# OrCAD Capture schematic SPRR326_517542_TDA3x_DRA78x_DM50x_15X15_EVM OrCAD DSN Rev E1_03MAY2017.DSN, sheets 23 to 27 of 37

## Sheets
23 SH31 - VIN HDMI IN-1: size C; rev: C1
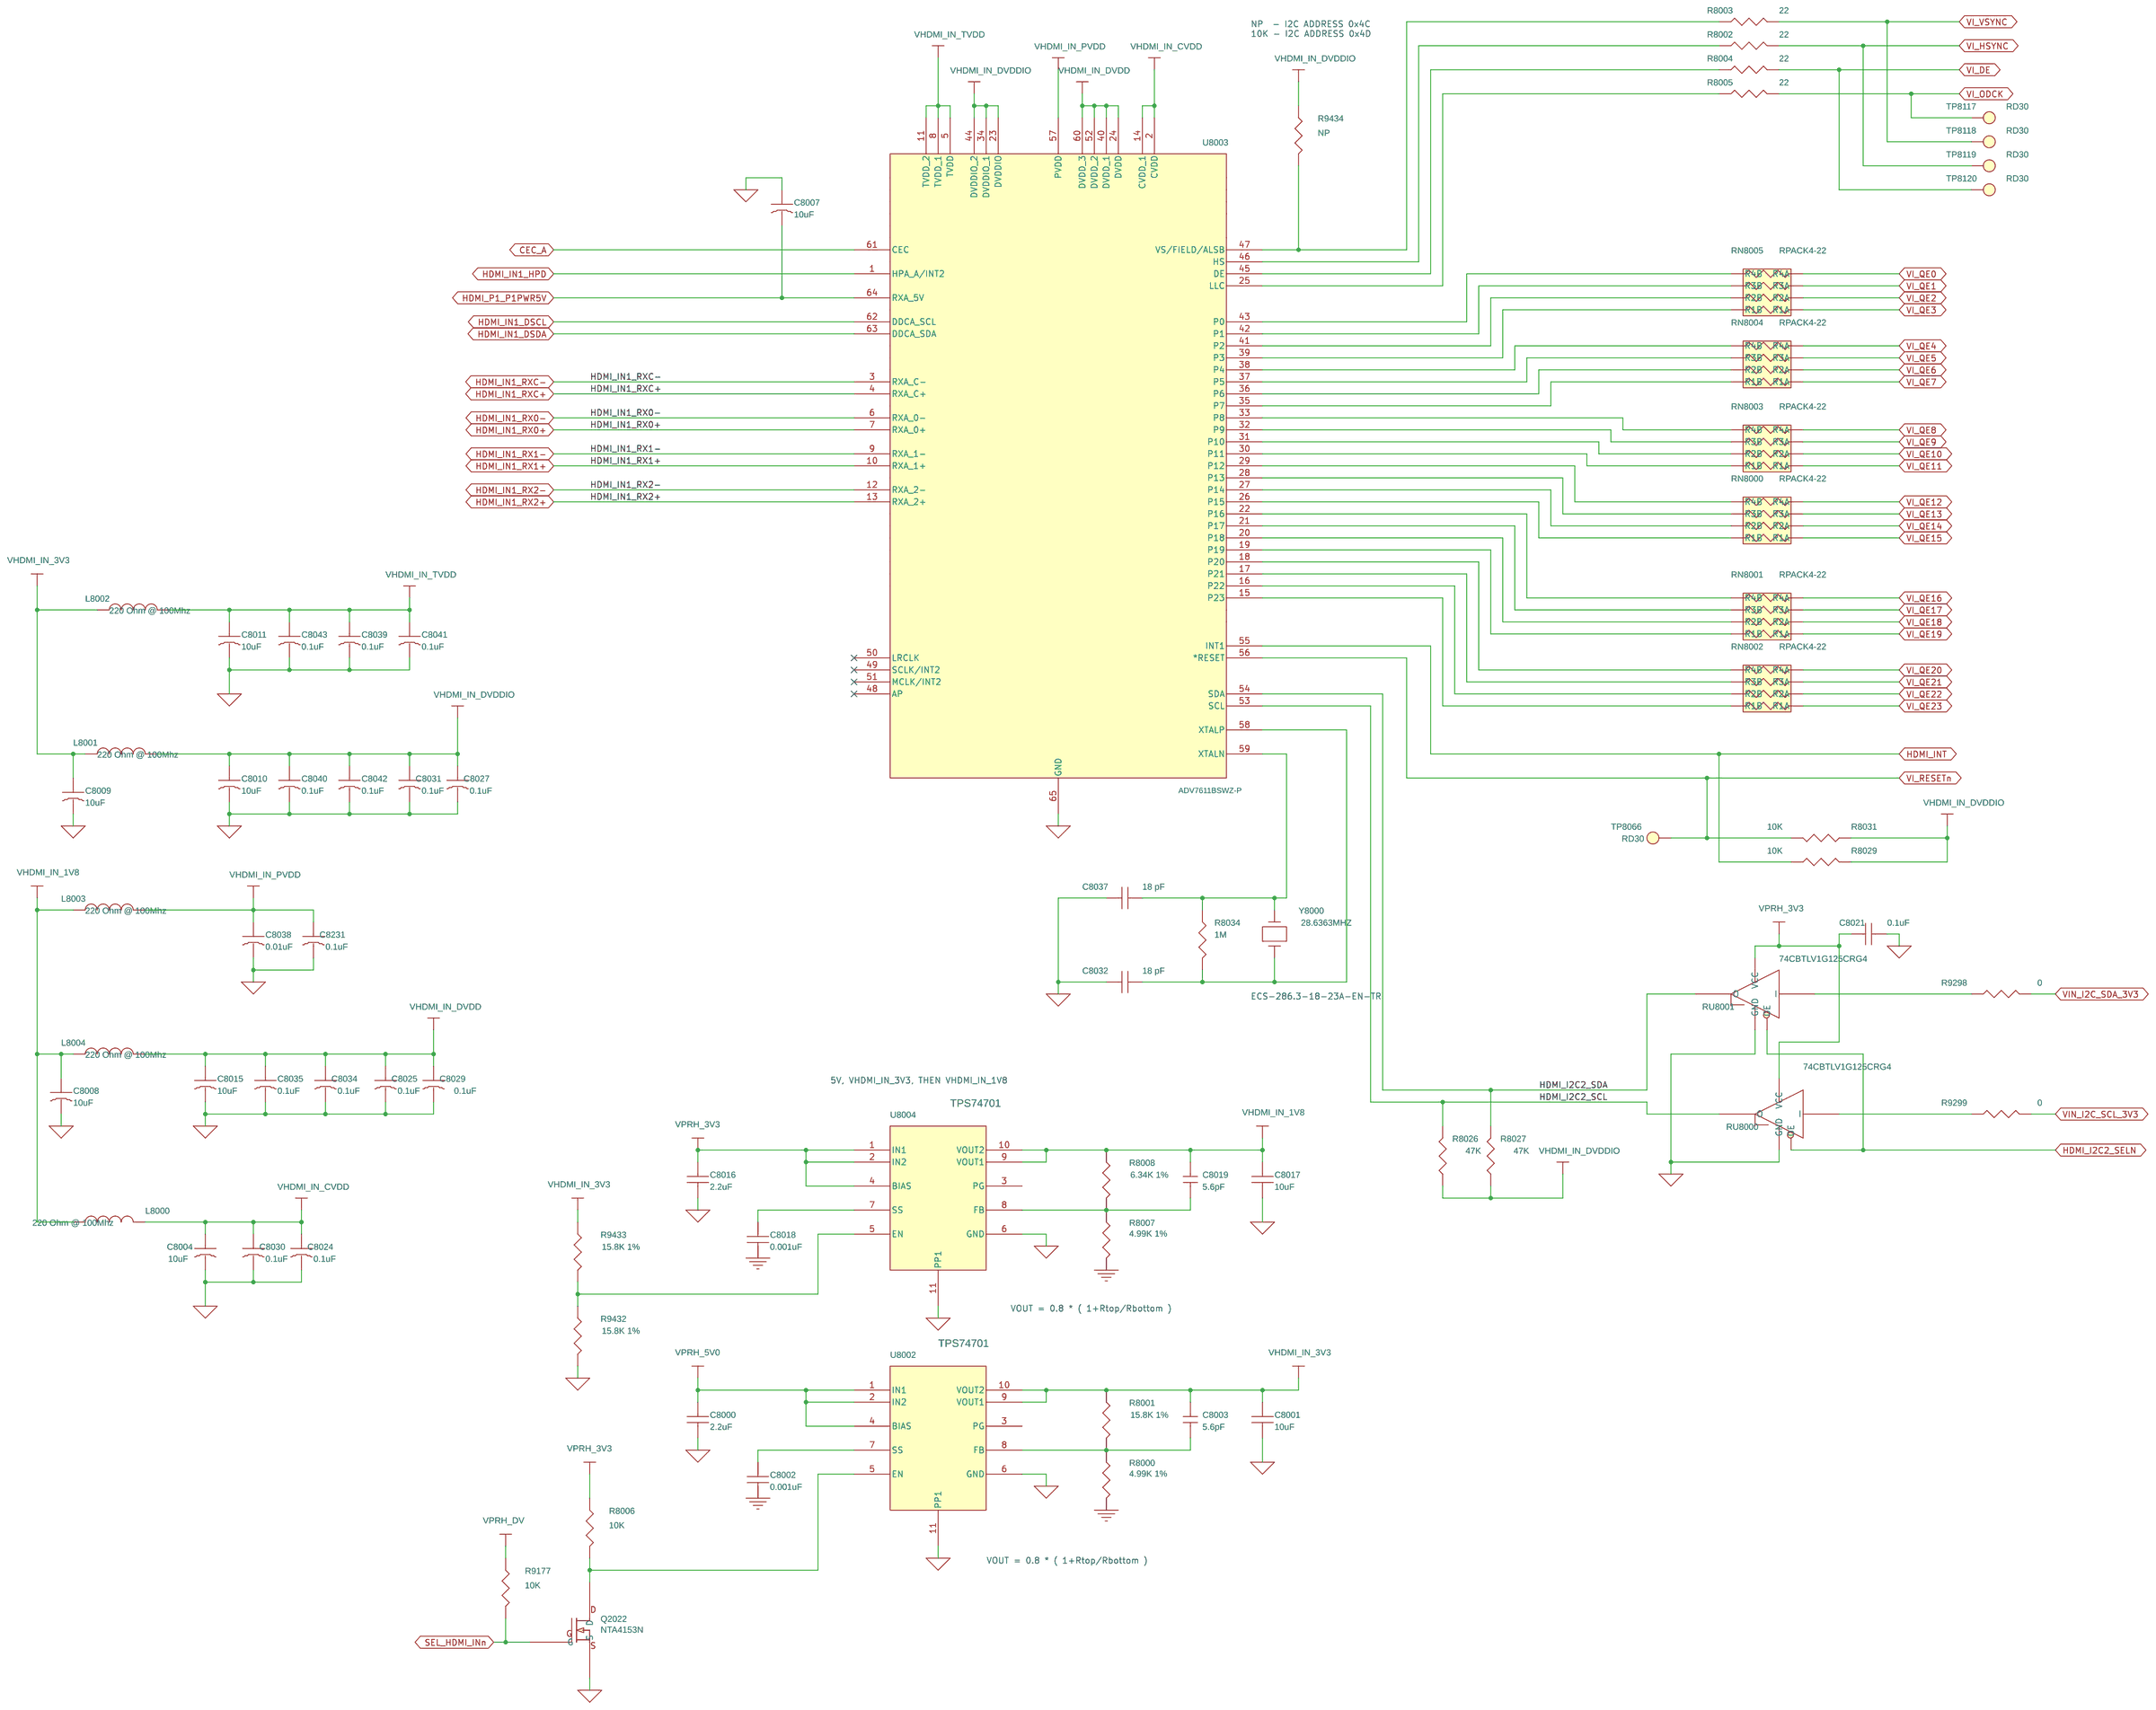
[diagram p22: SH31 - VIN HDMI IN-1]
24 SH32 - VIN HDMI IN-2: rev: B
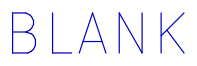
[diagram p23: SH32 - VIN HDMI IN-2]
25 SH33 - VIN HDMI IN-3: size C; rev: C1
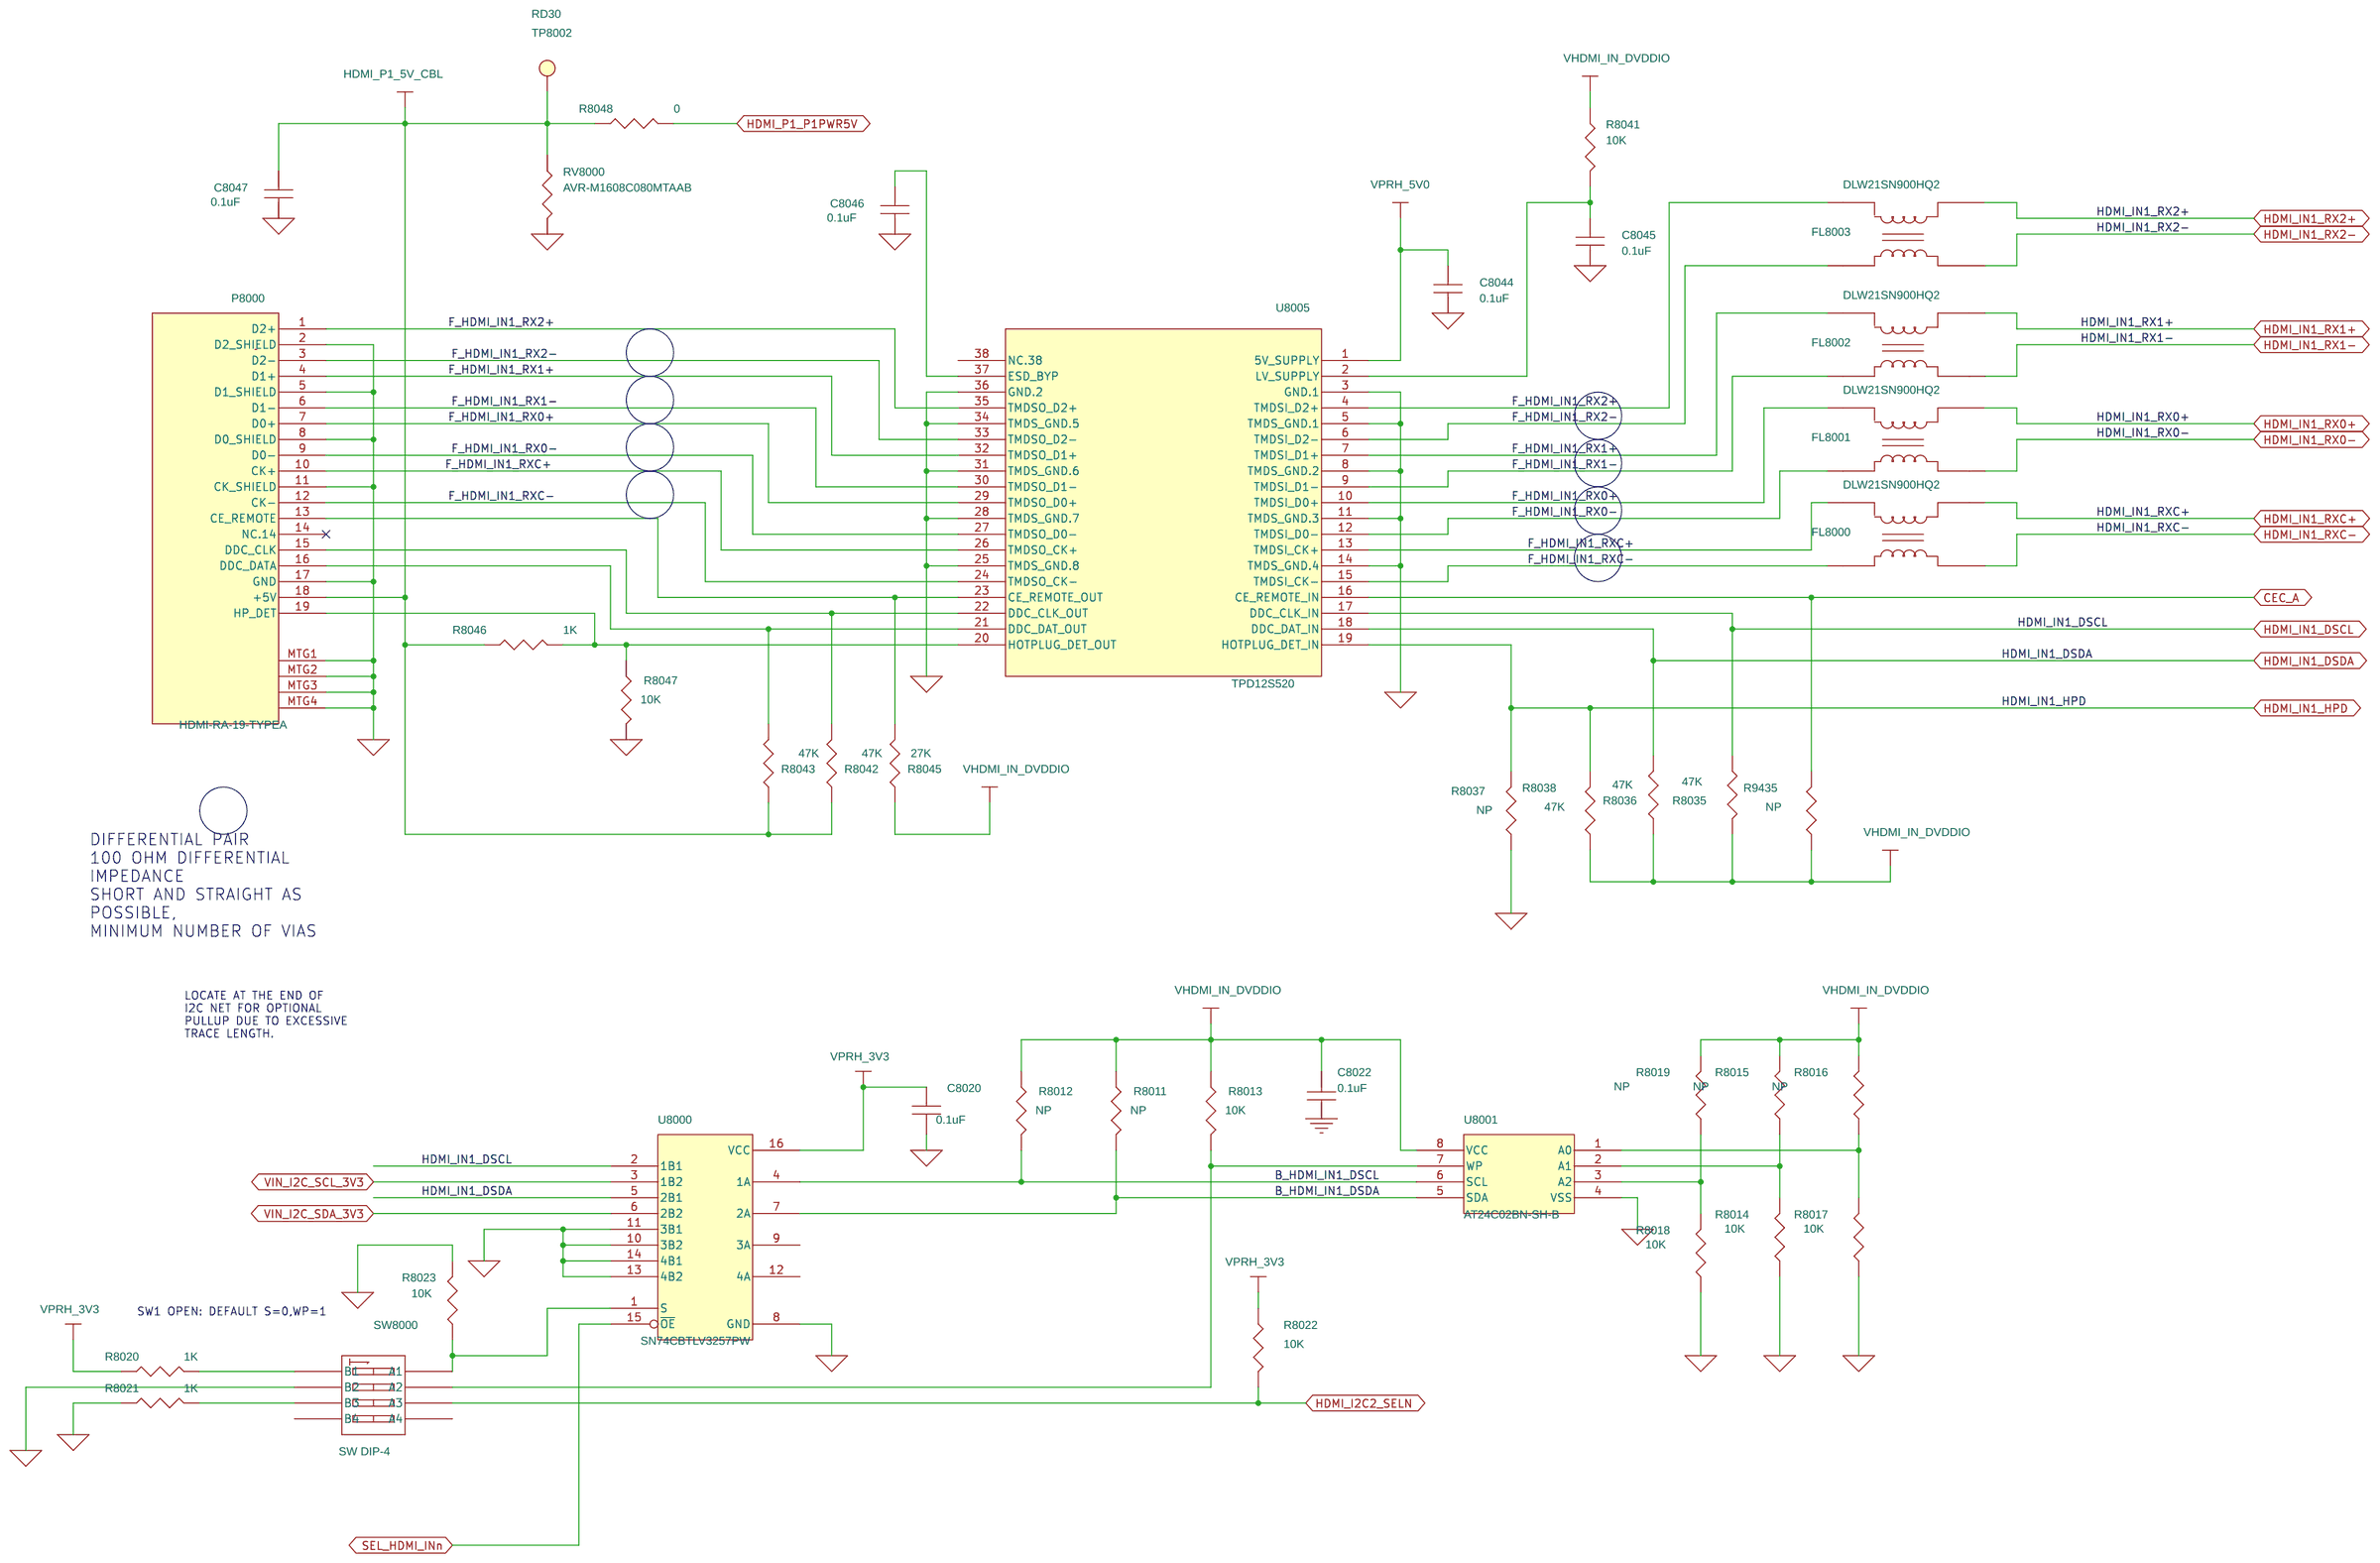
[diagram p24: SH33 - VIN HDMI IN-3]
26 SH34 - CPLD VOUT-1: size C; rev: B
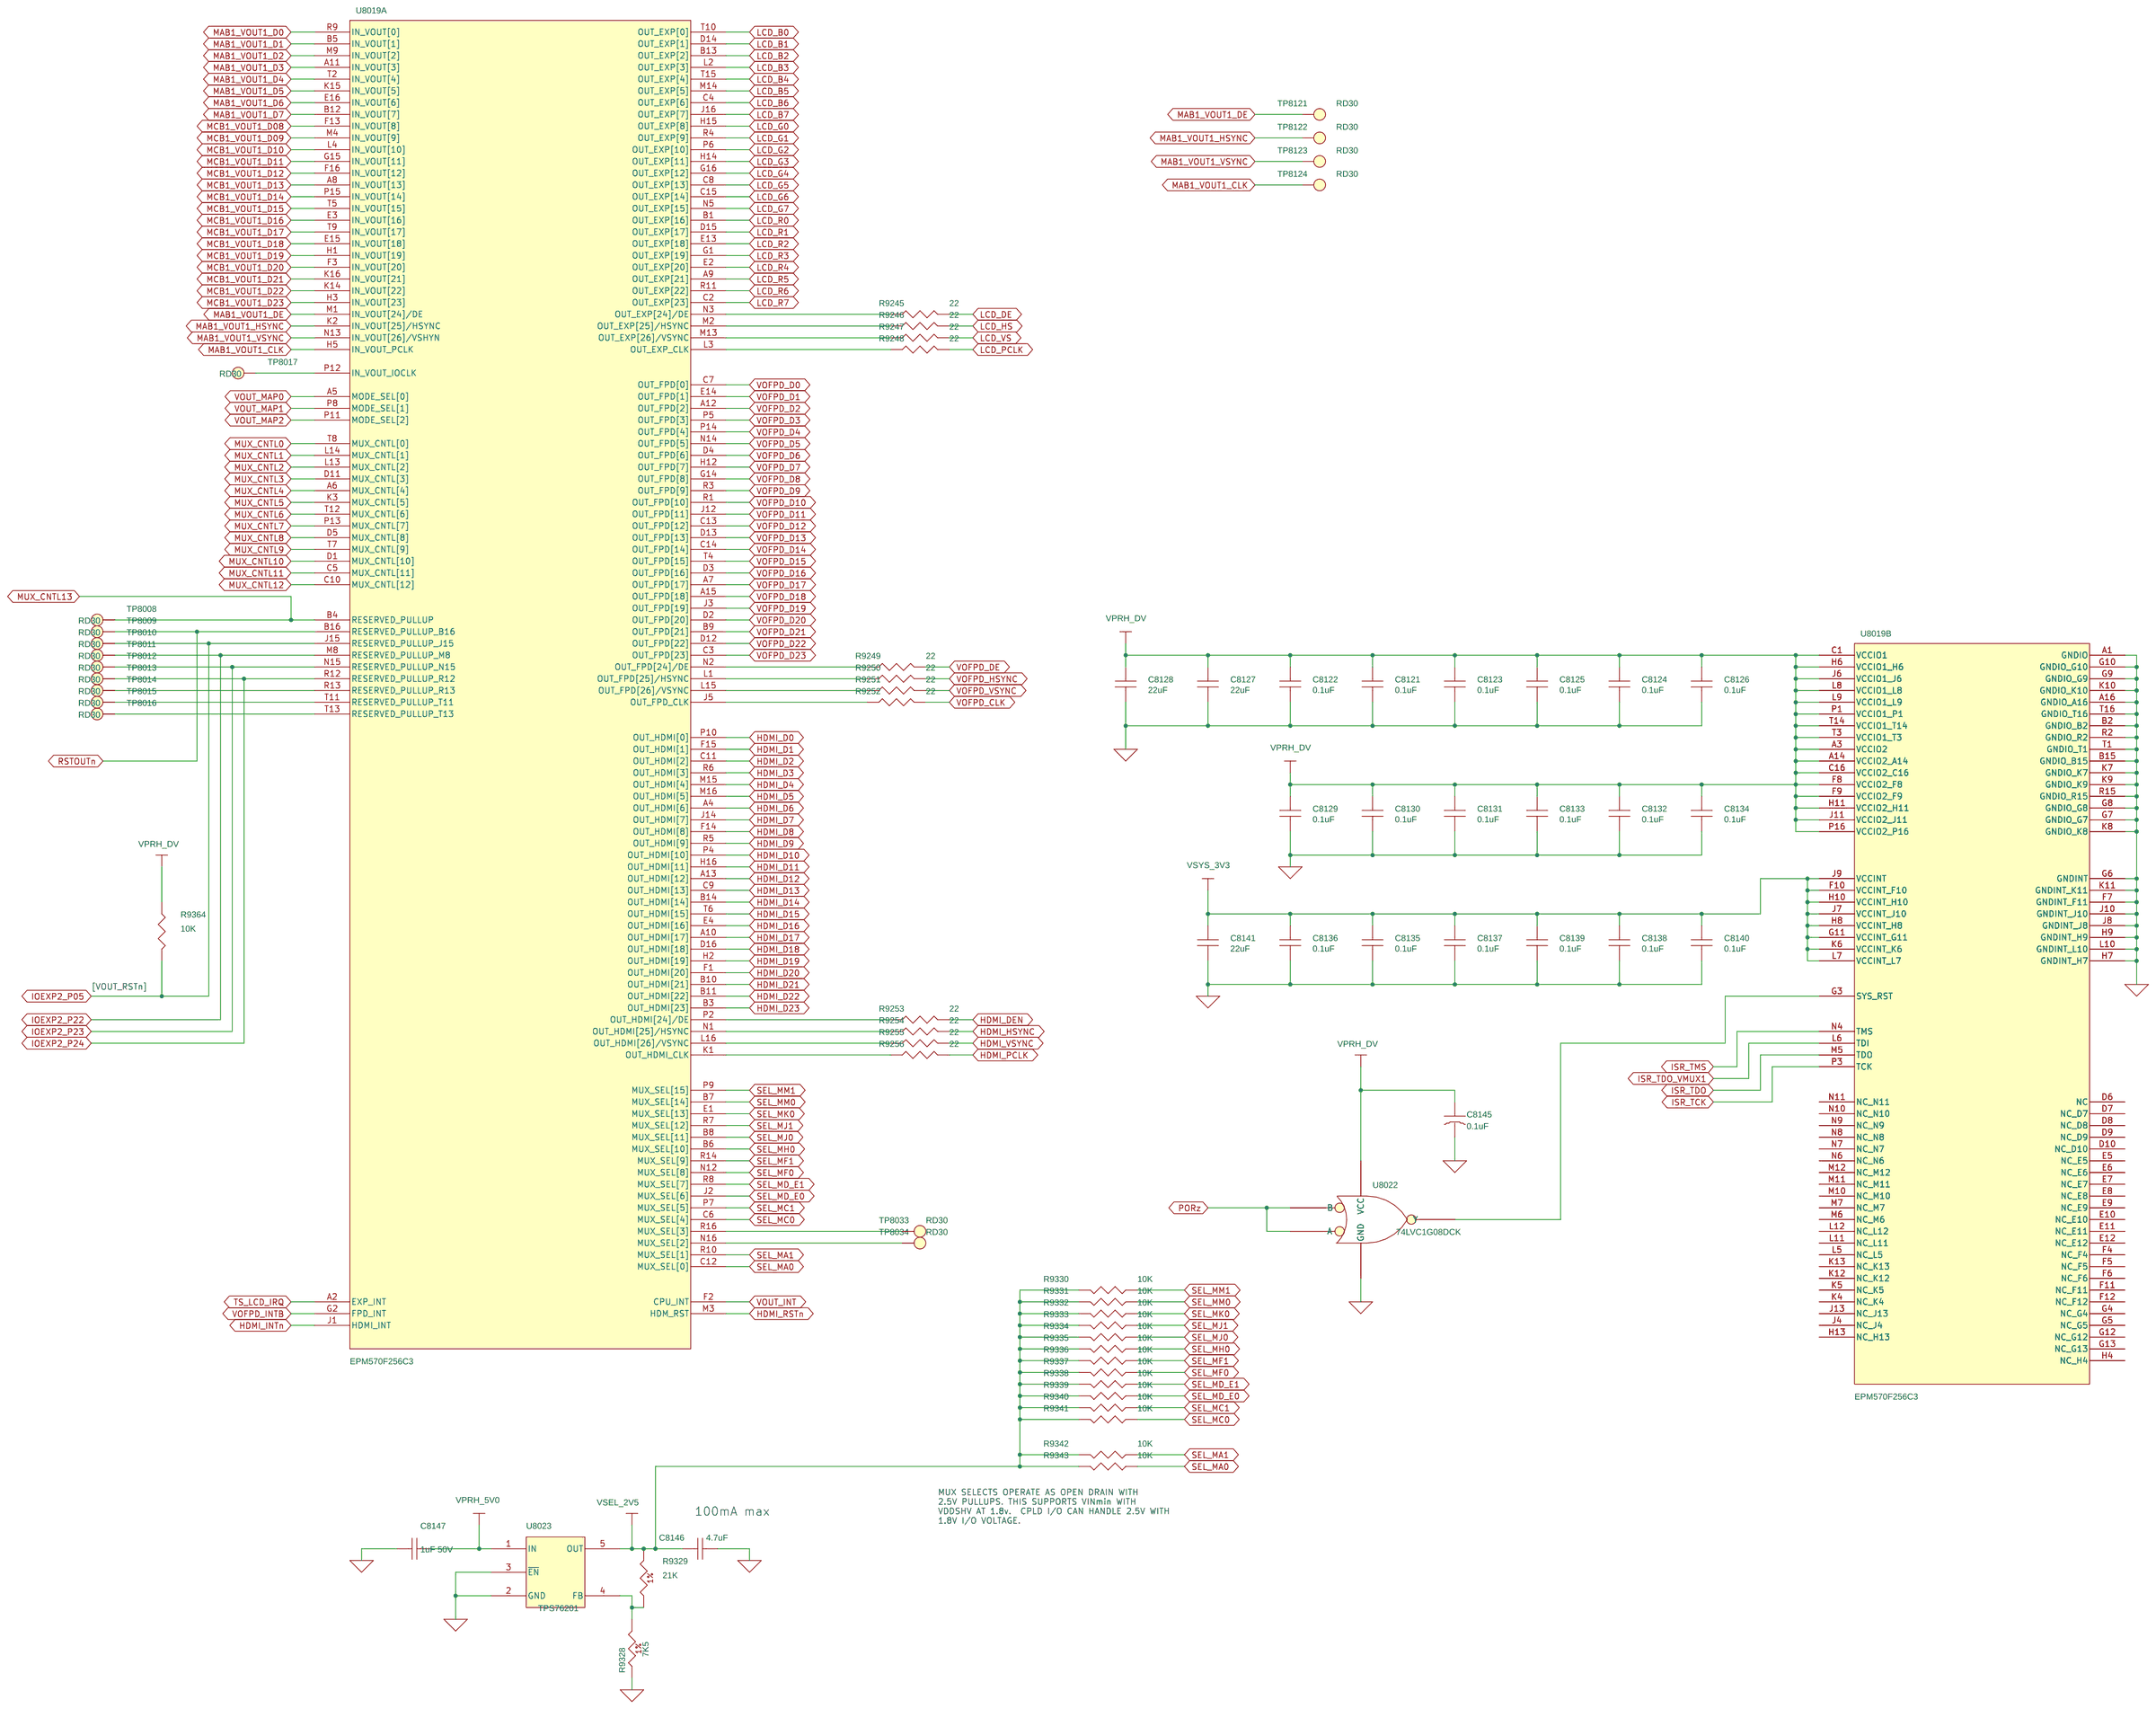
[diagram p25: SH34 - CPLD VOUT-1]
27 SH35 - CPLD VIN-1: size C; rev: B
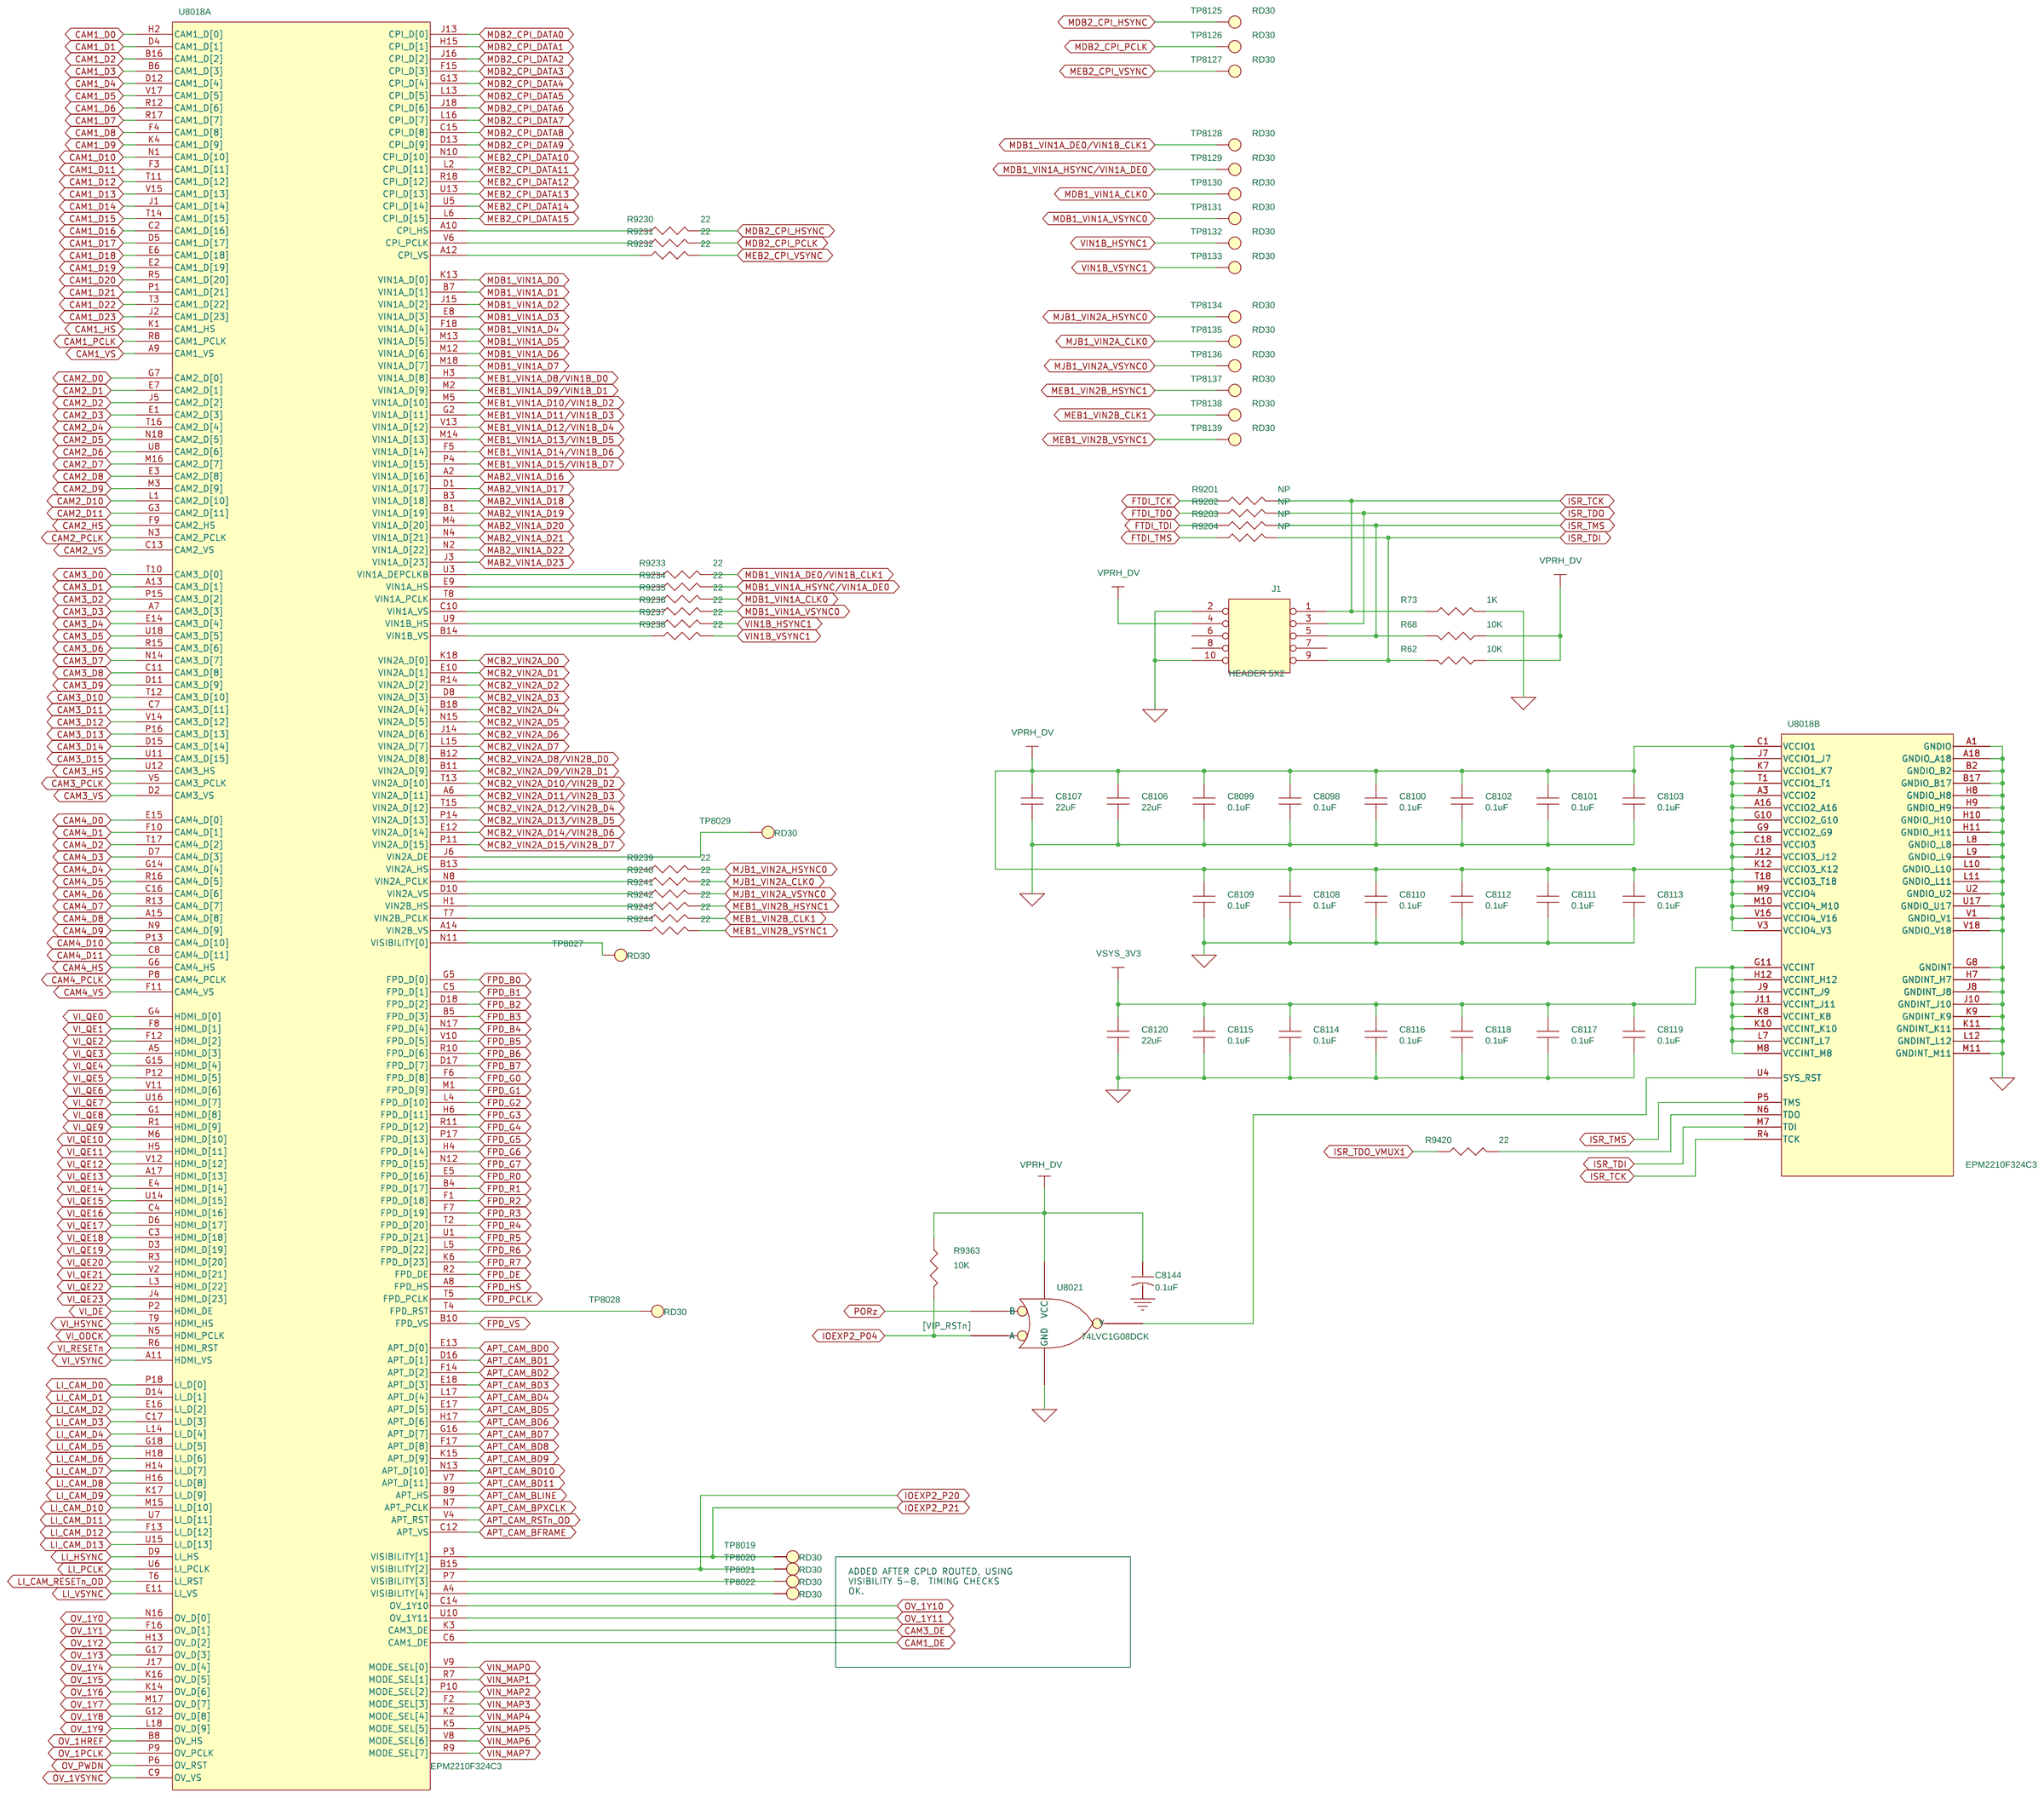
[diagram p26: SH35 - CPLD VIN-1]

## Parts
sheet SH31 - VIN HDMI IN-1
C8000  2.2uF  [c603-35x45]
C8001  10uF  [c603-35x45]
C8002  0.001uF  [c402-25]
C8003  5.6pF  [c402-25]
C8004  10uF  [c603-35x45]
C8007  10uF  [c603-35x45]
C8008  10uF  [c603-35x45]
C8009  10uF  [c603-35x45]
C8010  10uF  [c603-35x45]
C8011  10uF  [c603-35x45]
C8015  10uF  [c603-35x45]
C8016  2.2uF  [c603-35x45]
C8017  10uF  [c603-35x45]
C8018  0.001uF  [c402-25]
C8019  5.6pF  [c402-25]
C8021  0.1uF  [c402-25]
C8024  0.1uF  [c402-25]
C8025  0.1uF  [c402-25]
C8027  0.1uF  [c402-25]
C8029  0.1uF  [c402-25]
C8030  0.1uF  [c402-25]
C8031  0.1uF  [c402-25]
C8032  18 pF  [c402-25]
C8034  0.1uF  [c402-25]
C8035  0.1uF  [c402-25]
C8037  18 pF  [c402-25]
C8038  0.01uF  [c402-25]
C8039  0.1uF  [c402-25]
C8040  0.1uF  [c402-25]
C8041  0.1uF  [c402-25]
C8042  0.1uF  [c402-25]
C8043  0.1uF  [c402-25]
C8231  0.1uF  [c402-25]
L8000  220 Ohm @ 100Mhz  [l805-35x60]
L8001  220 Ohm @ 100Mhz  [l805-35x60]
L8002  220 Ohm @ 100Mhz  [l805-35x60]
L8003  220 Ohm @ 100Mhz  [l805-35x60]
L8004  220 Ohm @ 100Mhz  [l805-35x60]
Q2022  NTA4153N  [SC-75]
R8000  4.99K 1%  [r603-35x45]
R8001  15.8K 1%  [r603-35x45]
R8002  22  [r402-25]
R8003  22  [r402-25]
R8004  22  [r402-25]
R8005  22  [r402-25]
R8006  10K  [r402-25]
R8007  4.99K 1%  [r603-35x45]
R8008  6.34K 1%  [r603-35x45]
R8026  47K  [r402-25]
R8027  47K  [r402-25]
R8029  10K  [r402-25]
R8031  10K  [r402-25]
R8034  1M  [r402-25]
R9177  10K  [r402-25]
R9298  0  [r201-6p6spc]
R9299  0  [r201-6p6spc]
R9432  15.8K 1%  [r603-35x45]
R9433  15.8K 1%  [r603-35x45]
R9434  NP  [r402-25]
RN8000  RPACK4-22  [rpak8-10x25-28v]
RN8001  RPACK4-22  [rpak8-10x25-28v]
RN8002  RPACK4-22  [rpak8-10x25-28v]
RN8003  RPACK4-22  [rpak8-10x25-28v]
RN8004  RPACK4-22  [rpak8-10x25-28v]
RN8005  RPACK4-22  [rpak8-10x25-28v]
RU8000  74CBTLV1G125CRG4  [dck-5]
RU8001  74CBTLV1G125CRG4  [dck-5]
TP8066  RD30  [tp-30RD13]
TP8117  RD30  [tp-30RD13]
TP8118  RD30  [tp-30RD13]
TP8119  RD30  [tp-30RD13]
TP8120  RD30  [tp-30RD13]
U8002  TPS74701  [drc10-11x33]
U8003  ADV7611BSWZ-P  [lqfp64-10mm-sq-slug]
U8004  TPS74701  [drc10-11x33]
Y8000  28.6363MHZ  [xtal2-75x94]
sheet SH33 - VIN HDMI IN-3
C8020  0.1uF  [c402-25]
C8022  0.1uF  [c402-25]
C8044  0.1uF  [c402-25]
C8045  0.1uF  [c402-25]
C8046  0.1uF  [c402-25]
C8047  0.1uF  [c402-25]
FL8000  DLW21SN900HQ2  [EMI-36X15-DLW21]
FL8001  DLW21SN900HQ2  [EMI-36X15-DLW21]
FL8002  DLW21SN900HQ2  [EMI-36X15-DLW21]
FL8003  DLW21SN900HQ2  [EMI-36X15-DLW21]
P8000  HDMI-RA-19-TYPEA  [hdmi-smt-w-flange-rdpads]
R8011  NP  [r402-25]
R8012  NP  [r402-25]
R8013  10K  [r402-25]
R8014  10K  [r402-25]
R8015  NP  [r402-25]
R8016  NP  [r402-25]
R8017  10K  [r402-25]
R8018  10K  [r402-25]
R8019  NP  [r402-25]
R8020  1K  [r402-25]
R8021  1K  [r402-25]
R8022  10K  [r402-25]
R8023  10K  [r402-25]
R8035  47K  [r402-25]
R8036  47K  [r402-25]
R8037  NP  [r402-25]
R8038  47K  [r402-25]
R8041  10K  [r402-25]
R8042  47K  [r402-25]
R8043  47K  [r402-25]
R8045  27K  [r402-25]
R8046  1K  [r402-25]
R8047  10K  [r402-25]
R8048  0  [r402-25]
R9435  NP  [r402-25]
RV8000  AVR-M1608C080MTAAB  [r603-35x45]
SW8000  SW DIP-4  [sw4-30x50-tda]
TP8002  RD30  [tp-30RD13]
U8000  SN74CBTLV3257PW  [tssop16-14x70]
U8001  AT24C02BN-SH-B  [so8-25x75]
U8005  TPD12S520  [dbt38-12x70]
sheet SH34 - CPLD VOUT-1
C8121  0.1uF  [c402-25rd]
C8122  0.1uF  [c402-25rd]
C8123  0.1uF  [c402-25rd]
C8124  0.1uF  [c402-25rd]
C8125  0.1uF  [c402-25rd]
C8126  0.1uF  [c402-25rd]
C8127  22uF  [c1206-40x70]
C8128  22uF  [c1206-40x70]
C8129  0.1uF  [c402-25rd]
C8130  0.1uF  [c402-25rd]
C8131  0.1uF  [c402-25rd]
C8132  0.1uF  [c402-25rd]
C8133  0.1uF  [c402-25rd]
C8134  0.1uF  [c402-25rd]
C8135  0.1uF  [c402-25rd]
C8136  0.1uF  [c402-25rd]
C8137  0.1uF  [c402-25rd]
C8138  0.1uF  [c402-25rd]
C8139  0.1uF  [c402-25rd]
C8140  0.1uF  [c402-25rd]
C8141  22uF  [c1206-40x70]
C8145  0.1uF  [c402-25]
C8146  4.7uF  [C805-35X60]
C8147  1uF 50V  [c805-35x60]
R9245  22  [r402-25]
R9246  22  [r402-25]
R9247  22  [r402-25]
R9248  22  [r402-25]
R9249  22  [r402-25]
R9250  22  [r402-25]
R9251  22  [r402-25]
R9252  22  [r402-25]
R9253  22  [r402-25]
R9254  22  [r402-25]
R9255  22  [r402-25]
R9256  22  [r402-25]
R9328  7K5  [r603-35X45]
R9329  21K  [r603-35X45]
R9330  10K  [r402-25]
R9331  10K  [r402-25]
R9332  10K  [r402-25]
R9333  10K  [r402-25]
R9334  10K  [r402-25]
R9335  10K  [r402-25]
R9336  10K  [r402-25]
R9337  10K  [r402-25]
R9338  10K  [r402-25]
R9339  10K  [r402-25]
R9340  10K  [r402-25]
R9341  10K  [r402-25]
R9342  10K  [r402-25]
R9343  10K  [r402-25]
R9364  10K  [r402-25]
TP8008  RD30  [tp-30RD13]
TP8009  RD30  [tp-30RD13]
TP8010  RD30  [tp-30RD13]
TP8011  RD30  [tp-30RD13]
TP8012  RD30  [tp-30RD13]
TP8013  RD30  [tp-30RD13]
TP8014  RD30  [tp-30RD13]
TP8015  RD30  [tp-30RD13]
TP8016  RD30  [tp-30RD13]
TP8017  RD30  [tp-30RD13]
TP8033  RD30  [tp-30RD13]
TP8034  RD30  [tp-30RD13]
TP8121  RD30  [tp-30RD13]
TP8122  RD30  [tp-30RD13]
TP8123  RD30  [tp-30RD13]
TP8124  RD30  [tp-30RD13]
U8019  EPM570F256C3  [bga256-18rd]  (sections A,B)
U8022  74LVC1G08DCK  [dck-5]
U8023  TPS76201  [dbv-20x60-5]
sheet SH35 - CPLD VIN-1
C8098  0.1uF  [c402-25rd]
C8099  0.1uF  [c402-25rd]
C8100  0.1uF  [c402-25rd]
C8101  0.1uF  [c402-25rd]
C8102  0.1uF  [c402-25rd]
C8103  0.1uF  [c402-25rd]
C8106  22uF  [c1206-40x70]
C8107  22uF  [c1206-40x70]
C8108  0.1uF  [c402-25rd]
C8109  0.1uF  [c402-25rd]
C8110  0.1uF  [c402-25rd]
C8111  0.1uF  [c402-25rd]
C8112  0.1uF  [c402-25rd]
C8113  0.1uF  [c402-25rd]
C8114  0.1uF  [c402-25rd]
C8115  0.1uF  [c402-25rd]
C8116  0.1uF  [c402-25rd]
C8117  0.1uF  [c402-25rd]
C8118  0.1uF  [c402-25rd]
C8119  0.1uF  [c402-25rd]
C8120  22uF  [c1206-40x70]
C8144  0.1uF  [c402-25]
J1  HEADER 5X2  [JUMP2X5-6040]
R62  10K  [r402-25]
R68  10K  [r402-25]
R73  1K  [r402-25]
R9201  NP  [r402-25]
R9202  NP  [r402-25]
R9203  NP  [r402-25]
R9204  NP  [r402-25]
R9230  22  [r402-25]
R9231  22  [r402-25]
R9232  22  [r402-25]
R9233  22  [r402-25]
R9234  22  [r402-25]
R9235  22  [r402-25]
R9236  22  [r402-25]
R9237  22  [r402-25]
R9238  22  [r402-25]
R9239  22  [r402-25]
R9240  22  [r402-25]
R9241  22  [r402-25]
R9242  22  [r402-25]
R9243  22  [r402-25]
R9244  22  [r402-25]
R9363  10K  [r402-25]
R9420  22  [r402-25]
TP8019  RD30  [tp-30RD13]
TP8020  RD30  [tp-30RD13]
TP8021  RD30  [tp-30RD13]
TP8022  RD30  [tp-30RD13]
TP8027  RD30  [tp-30RD13]
TP8028  RD30  [tp-30RD13]
TP8029  RD30  [tp-30RD13]
TP8125  RD30  [tp-30RD13]
TP8126  RD30  [tp-30RD13]
TP8127  RD30  [tp-30RD13]
TP8128  RD30  [tp-30RD13]
TP8129  RD30  [tp-30RD13]
TP8130  RD30  [tp-30RD13]
TP8131  RD30  [tp-30RD13]
TP8132  RD30  [tp-30RD13]
TP8133  RD30  [tp-30RD13]
TP8134  RD30  [tp-30RD13]
TP8135  RD30  [tp-30RD13]
TP8136  RD30  [tp-30RD13]
TP8137  RD30  [tp-30RD13]
TP8138  RD30  [tp-30RD13]
TP8139  RD30  [tp-30RD13]
U8018  EPM2210F324C3  [bga324-18rd]  (sections A,B)
U8021  74LVC1G08DCK  [dck-5]

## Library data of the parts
C8000 C8016 = CAP_NP: Part #: 104448-0220R
C8001 C8017 = CAP_NP: Part #: 102963-0101R
C8002 C8018 = CAP_NP: Part #: 102058-1102R
C8003 C8019 = Cap_100nF_Cermc_16V_10%_603_0: 3pF Capacitor, Ceramic, 16V, 10%, 0402; Part #: 101782-1565R; PartName: Cap 3pF Cermc 16V 10% 402; SD PCB Footprint: EIA0402
C8004 C8007-C8011 C8015 = CAP: Part #: 102963-0101R
C8020 C8021 C8044-C8047 = CAP_NP: Part #: 104446-1100R
C8024 C8025 C8027 C8029-C8031 C8034 C8035 C8039-C8043 C8231 = CAP: Capacitor,0.1UF, X7R, 16 V, 0402, 10%; PARTNUM: 100-00108; Part #: 104446-1100R; Tolerance: 10%; Vendor: KEMET; Datasheet: http://www.kemet.com/kemet/web/homepage/kechome.nsf/vapubfiles/F3102X7R.pdf/$file/F3102X7R.pdf
C8032 C8037 = CAP_NP_3: Part #: 101782-1184R; SD PCB Footprint: EIA0603
C8038 = CAP: Capacitor,0.1UF, X7R, 16 V, 0402, 10%; PARTNUM: 100-00108; Part #: 101587-1101R; Tolerance: 10%; Vendor: KEMET; Datasheet: http://www.kemet.com/kemet/web/homepage/kechome.nsf/vapubfiles/F3102X7R.pdf/$file/F3102X7R.pdf
L8000-L8004 = INDUCTOR_0: Part #: 101228-2201R
Q2022 = NTA4153N: Part #: 102437-0001R
R8000 R8007 = R_3: Part #: 100642-4992R
R8001 R9432 R9433 = R_3: Part #: 100642-1583R
R8002-R8005 R9230-R9256 R9420 = R_1: Part #: 101370-2200R
R8006 R9177 = 10KOhmResistor1_16W0402: Part #: 101370-1003R
R8008 = R_3: Part #: 100642-6342R
R8026 R8027 R8035 R8036 R8038 R8042 R8043 = R: Part #: 101370-4703R
R8029 = R_1: Part #: 101370-1003R
R62 R68 R8022 R8023 R8031 R9363 R9364 = RESISTOR_0: Part #: 101370-1003R
R8034 = R_1: Part #: 101370-1005R
R9298 R9299 = R_1: Part #: 103158-0001R
R9434 = 10KOhmResistor1_16W0402: Part #: R0402-NOPOP
RN8000-RN8005 = R-Pak4_0: Part #: 101327-2200R
RU8000 RU8001 = SN74LVC1G125: Part #: 101689-0125R
TP8002 TP8066 TP8117-TP8120 = TESTPOINT_1: Part #: TP-30RD13-NO-POP
U8002 U8004 = U-TPS78601_AJUST_-_1_0.5A_LDO: Part #: 102752-0001R
U8003 = ADV7611BSWZ-P: Part #: 104496-0001R
Y8000 = CRYSTAL_0: Part #: 104519-2863R; VendorNum: CS325S-28.6363MABJT
C8022 = CAP_.1_uF_10%_0603: Part #: 104446-1100R; SD PCB Footprint: EIA0603
FL8000-FL8003 = DLW21SN900HQ2: Part #: 104184-9000R
P8000 = HDMI-RA-19_0: Part #: 103169-0001R
R8011 R8012 R8037 R9201-R9204 R9435 = R: Part #: R0402-NOPOP
R8013 R8041 R8047 R9330-R9343 = R: Part #: 101370-1003R
R8014 R8017 R8018 = R_0: Part #: 101370-1003R
R8015 R8016 R8019 = R_0: Part #: R0402-NOPOP
R73 R8020 R8021 R8046 = R: Part #: 101370-1002R
R8045 = R: Part #: 101370-2703R
R8048 = R_1: Part #: 101370-0001R
RV8000 = R: Part #: 103423-0001R
SW8000 = SW_DIP-4_0: Part #: 101184-0004R
U8000 = SN74CBT3257PW: Part #: 101670-0001R
U8001 = 24WC256_0: 256K-Bit I 2 C Serial CMOS EEPROM; Part #: 103451-0001R; SD PCB Footprint: SO8W
U8005 = TPD12S520: Part #: 103422-0001R
C8098-C8103 C8108-C8119 C8121-C8126 C8129-C8140 = CAP_AM_0402_0.1uf_x7r_16v_10%_X: Part #: 104446-1100R
C8106 C8107 C8120 C8127 C8128 C8141 = CAP_AM_1206_22uf_x7r_6.3v_20_X: Part #: 104463-0221R
C8144 C8145 = CAP: Part #: 104446-1100R
C8146 = X5R_04.7uF_6.3V: Part #: 101063-0470R
C8147 = X5R_001uF_10V: Part #: 100201-0100R
R9328 = 0603_1%_007.5K: Part #: 100642-7502R
R9329 = 0603_1%_021K: Part #: 100642-2103R
TP8008-TP8017 TP8019-TP8022 TP8027-TP8029 TP8033 TP8034 TP8121-TP8139 = TESTPOINT: Part #: TP-30RD13-NO-POP
U8019 = video_out_mux: Part #: 104468-0001R
U8021 U8022 = 1G08: Part #: 101057-0008R
U8023 = LDO_TPS76201_ADJ_100mA: Part #: 104459-0001R
J1 = HEADER_5X2_0: Part #: 100116-0005R
U8018 = vin_mux: Part #: 104467-0001R

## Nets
GND: C8000.2 C8001.2 C8002.2 C8004.2 C8007.1 C8008.2 C8009.2 C8010.2 C8011.2 C8015.2 C8016.2 C8017.2 C8018.2 C8020.2 C8021.2 C8022.1 C8024.2 C8025.2 C8027.2 C8029.2 C8030.2 C8031.2 C8032.2 C8034.2 C8035.2 C8037.2 C8038.2 C8039.2 C8040.2 C8041.2 C8042.2 C8043.2 C8044.2 C8045.2 C8046.2 C8047.2 C8098.2 C8099.2 C8100.2 C8101.2 C8102.2 C8103.2 C8106.2 C8107.2 C8108.2 C8109.2 C8110.2 C8111.2 C8112.2 C8113.2 C8114.2 C8115.2 C8116.2 C8117.2 C8118.2 C8119.2 C8120.2 C8121.2 C8122.2 C8123.2 C8124.2 C8125.2 C8126.2 C8127.2 C8128.2 C8129.2 C8130.2 C8131.2 C8132.2 C8133.2 C8134.2 C8135.2 C8136.2 C8137.2 C8138.2 C8139.2 C8140.2 C8141.2 C8144.2 C8145.2 C8146.2 C8147.1 C8231.2 J1.2 J1.10 P8000.2(D2_SHIELD) P8000.5(D1_SHIELD) P8000.8(D0_SHIELD) P8000.11(CK_SHIELD) P8000.17(GND) P8000.MTG1 P8000.MTG2 P8000.MTG3 P8000.MTG4 Q2022.2(S) R73.1 R8000.2 R8007.2 R8014.2 R8017.2 R8018.2 R8021.2 R8023.1 R8037.2 R8047.2 R9328.1 R9432.2 RU8000.3(GND) RU8001.3(GND) RV8000.1 SW8000.7(B2) U8000.8(GND) U8000.10(3B2) U8000.11(3B1) U8000.13(4B2) U8000.14(4B1) U8001.4(VSS) U8002.6(GND) U8002.11(PP1) U8003.65(GND) U8004.6(GND) U8004.11(PP1) U8005.3(GND.1) U8005.5(TMDS_GND.1) U8005.8(TMDS_GND.2) U8005.11(TMDS_GND.3) U8005.14(TMDS_GND.4) U8005.25(TMDS_GND.8) U8005.28(TMDS_GND.7) U8005.31(TMDS_GND.6) U8005.34(TMDS_GND.5) U8005.36(GND.2) U8018.A1(GNDIO) U8018.A18(GNDIO) U8018.B2(GNDIO) U8018.B17(GNDIO) U8018.G8(GNDINT) U8018.H7(GNDINT) U8018.H8(GNDIO) U8018.H9(GNDIO) U8018.H10(GNDIO) U8018.H11(GNDIO) U8018.J8(GNDINT) U8018.J10(GNDINT) U8018.K9(GNDINT) U8018.K11(GNDINT) U8018.L8(GNDIO) U8018.L9(GNDIO) U8018.L10(GNDIO) U8018.L11(GNDIO) U8018.L12(GNDINT) U8018.M11(GNDINT) U8018.U2(GNDIO) U8018.U17(GNDIO) U8018.V1(GNDIO) U8018.V18(GNDIO) U8019.A1(GNDIO) U8019.A16(GNDIO) U8019.B2(GNDIO) U8019.B15(GNDIO) U8019.F7(GNDINT_F11) U8019.G6(GNDINT) U8019.G7(GNDIO) U8019.G8(GNDIO) U8019.G9(GNDIO) U8019.G10(GNDIO) U8019.H7(GNDINT) U8019.H9(GNDINT) U8019.J8(GNDINT) U8019.J10(GNDINT) U8019.K7(GNDIO) U8019.K8(GNDIO) U8019.K9(GNDIO) U8019.K10(GNDIO) U8019.K11(GNDINT) U8019.L10(GNDINT) U8019.R2(GNDIO) U8019.R15(GNDIO) U8019.T1(GNDIO) U8019.T16(GNDIO) U8021.3(GND) U8022.3(GND) U8023.2(GND) U8023.3(~{EN}) ; also on sheet 4 5 6 7 8 9 10 11 12 13 14 15 16 17 18 19 20 21 22 28 29 30 31 32 34 35 36 37
MCB2_VIN2A_D8/VIN2B_D0: U8018.B12(VIN2A_D[8]) ; also on sheet 30
MCB2_VIN2A_D9/VIN2B_D1: U8018.B11(VIN2A_D[9]) ; also on sheet 30
MCB2_VIN2A_D10/VIN2B_D2: U8018.T13(VIN2A_D[10]) ; also on sheet 30
MCB2_VIN2A_D11/VIN2B_D3: U8018.A6(VIN2A_D[11]) ; also on sheet 30
MCB2_VIN2A_D12/VIN2B_D4: U8018.T15(VIN2A_D[12]) ; also on sheet 30
MCB2_VIN2A_D13/VIN2B_D5: U8018.P14(VIN2A_D[13]) ; also on sheet 30
MCB2_VIN2A_D14/VIN2B_D6: U8018.E12(VIN2A_D[14]) ; also on sheet 30
MCB2_VIN2A_D15/VIN2B_D7: U8018.P11(VIN2A_D[15]) ; also on sheet 30
MDB1_VIN1A_DE0/VIN1B_CLK1: R9233.2 TP8128.1(TP) ; also on sheet 34
MDB1_VIN1A_HSYNC/VIN1A_DE0: R9234.2 TP8129.1(TP) ; also on sheet 34
MEB1_VIN1A_D8/VIN1B_D0: U8018.H3(VIN1A_D[8]) ; also on sheet 34
MEB1_VIN1A_D9/VIN1B_D1: U8018.M2(VIN1A_D[9]) ; also on sheet 34
MEB1_VIN1A_D10/VIN1B_D2: U8018.M5(VIN1A_D[10]) ; also on sheet 34
MEB1_VIN1A_D11/VIN1B_D3: U8018.G2(VIN1A_D[11]) ; also on sheet 34
MEB1_VIN1A_D12/VIN1B_D4: U8018.V13(VIN1A_D[12]) ; also on sheet 34
MEB1_VIN1A_D13/VIN1B_D5: U8018.M14(VIN1A_D[13]) ; also on sheet 34
MEB1_VIN1A_D14/VIN1B_D6: U8018.F5(VIN1A_D[14]) ; also on sheet 34
MEB1_VIN1A_D15/VIN1B_D7: U8018.P4(VIN1A_D[15]) ; also on sheet 34
R_MCAN_TX/VIN2A_DE0/VIN2A_HYSNC0/SPI1_CS2/UART3_RXD/QSPI1_CS1/GMPC_WAIT1/VIN1B_HSYNC1: R9237.2 TP8132.1(TP) ; also on sheet 7
VIN_I2C_SCL_3V3: R9299.2 U8000.3(1B2) ; also on sheet 19 20 21 31
VIN_I2C_SDA_3V3: R9298.2 U8000.6(2B2) ; also on sheet 19 20 21 31
VIN_MAP0: U8018.V9(MODE_SEL[0]) ; also on sheet 8
VIN_MAP1: U8018.R7(MODE_SEL[1]) ; also on sheet 8
VIN_MAP2: U8018.P10(MODE_SEL[2]) ; also on sheet 8
VIN_MAP3: U8018.F2(MODE_SEL[3]) ; also on sheet 8
VIN_MAP4: U8018.K2(MODE_SEL[4]) ; also on sheet 8
VIN_MAP5: U8018.K5(MODE_SEL[5]) ; also on sheet 8
VIN_MAP6: U8018.V8(MODE_SEL[6]) ; also on sheet 8
VIN_MAP7: U8018.R9(MODE_SEL[7]) ; also on sheet 8
APT_CAM_BD0: U8018.E13(APT_D[0]) ; also on sheet 21
APT_CAM_BD1: U8018.D16(APT_D[1]) ; also on sheet 21
APT_CAM_BD2: U8018.F14(APT_D[2]) ; also on sheet 21
APT_CAM_BD3: U8018.E18(APT_D[3]) ; also on sheet 21
APT_CAM_BD4: U8018.L17(APT_D[4]) ; also on sheet 21
APT_CAM_BD5: U8018.E17(APT_D[5]) ; also on sheet 21
APT_CAM_BD6: U8018.H17(APT_D[6]) ; also on sheet 21
APT_CAM_BD7: U8018.G16(APT_D[7]) ; also on sheet 21
APT_CAM_BD8: U8018.F17(APT_D[8]) ; also on sheet 21
APT_CAM_BD9: U8018.K15(APT_D[9]) ; also on sheet 21
APT_CAM_BD10: U8018.N13(APT_D[10]) ; also on sheet 21
APT_CAM_BD11: U8018.V7(APT_D[11]) ; also on sheet 21
APT_CAM_BFRAME: U8018.C12(APT_VS) ; also on sheet 21
APT_CAM_BLINE: U8018.B9(APT_HS) ; also on sheet 21
APT_CAM_BPXCLK: U8018.N7(APT_PCLK) ; also on sheet 21
APT_CAM_RSTn_OD: U8018.V4(APT_RST) ; also on sheet 21
B_HDMI_IN1_DSCL: R8012.2 U8000.4(1A) U8001.6(SCL)
B_HDMI_IN1_DSDA: R8011.2 U8000.7(2A) U8001.5(SDA)
CAM1_D0: U8018.H2(CAM1_D[0]) ; also on sheet 21
CAM1_D1: U8018.D4(CAM1_D[1]) ; also on sheet 21
CAM1_D2: U8018.B16(CAM1_D[2]) ; also on sheet 21
CAM1_D3: U8018.B6(CAM1_D[3]) ; also on sheet 21
CAM1_D4: U8018.D12(CAM1_D[4]) ; also on sheet 21
CAM1_D5: U8018.V17(CAM1_D[5]) ; also on sheet 21
CAM1_D6: U8018.R12(CAM1_D[6]) ; also on sheet 21
CAM1_D7: U8018.R17(CAM1_D[7]) ; also on sheet 21
CAM1_D8: U8018.F4(CAM1_D[8]) ; also on sheet 21
CAM1_D9: U8018.K4(CAM1_D[9]) ; also on sheet 21
CAM1_D10: U8018.N1(CAM1_D[10]) ; also on sheet 21
CAM1_D11: U8018.F3(CAM1_D[11]) ; also on sheet 21
CAM1_D12: U8018.T11(CAM1_D[12]) ; also on sheet 21
CAM1_D13: U8018.V15(CAM1_D[13]) ; also on sheet 21
CAM1_D14: U8018.J1(CAM1_D[14]) ; also on sheet 21
CAM1_D15: U8018.T14(CAM1_D[15]) ; also on sheet 21
CAM1_D16: U8018.C2(CAM1_D[16]) ; also on sheet 21
CAM1_D17: U8018.D5(CAM1_D[17]) ; also on sheet 21
CAM1_D18: U8018.E6(CAM1_D[18]) ; also on sheet 21
CAM1_D19: U8018.E2(CAM1_D[19]) ; also on sheet 21
CAM1_D20: U8018.R5(CAM1_D[20]) ; also on sheet 21
CAM1_D21: U8018.P1(CAM1_D[21]) ; also on sheet 21
CAM1_D22: U8018.T3(CAM1_D[22]) ; also on sheet 21
CAM1_D23: U8018.J2(CAM1_D[23]) ; also on sheet 21
CAM1_DE: U8018.C6(CAM1_DE) ; also on sheet 21
CAM1_HS: U8018.K1(CAM1_HS) ; also on sheet 21
CAM1_PCLK: U8018.R8(CAM1_PCLK) ; also on sheet 21
CAM1_VS: U8018.A9(CAM1_VS) ; also on sheet 21
CAM2_D0: U8018.G7(CAM2_D[0]) ; also on sheet 21
CAM2_D1: U8018.E7(CAM2_D[1]) ; also on sheet 21
CAM2_D2: U8018.J5(CAM2_D[2]) ; also on sheet 21
CAM2_D3: U8018.E1(CAM2_D[3]) ; also on sheet 21
CAM2_D4: U8018.T16(CAM2_D[4]) ; also on sheet 21
CAM2_D5: U8018.N18(CAM2_D[5]) ; also on sheet 21
CAM2_D6: U8018.U8(CAM2_D[6]) ; also on sheet 21
CAM2_D7: U8018.M16(CAM2_D[7]) ; also on sheet 21
CAM2_D8: U8018.E3(CAM2_D[8]) ; also on sheet 21
CAM2_D9: U8018.M3(CAM2_D[9]) ; also on sheet 21
CAM2_D10: U8018.L1(CAM2_D[10]) ; also on sheet 21
CAM2_D11: U8018.G3(CAM2_D[11]) ; also on sheet 21
CAM2_HS: U8018.F9(CAM2_HS) ; also on sheet 21
CAM2_PCLK: U8018.N3(CAM2_PCLK) ; also on sheet 21
CAM2_VS: U8018.C13(CAM2_VS) ; also on sheet 21
CAM3_D0: U8018.T10(CAM3_D[0]) ; also on sheet 21
CAM3_D1: U8018.A13(CAM3_D[1]) ; also on sheet 21
CAM3_D2: U8018.P15(CAM3_D[2]) ; also on sheet 21
CAM3_D3: U8018.A7(CAM3_D[3]) ; also on sheet 21
CAM3_D4: U8018.E14(CAM3_D[4]) ; also on sheet 21
CAM3_D5: U8018.U18(CAM3_D[5]) ; also on sheet 21
CAM3_D6: U8018.R15(CAM3_D[6]) ; also on sheet 21
CAM3_D7: U8018.N14(CAM3_D[7]) ; also on sheet 21
CAM3_D8: U8018.C11(CAM3_D[8]) ; also on sheet 21
CAM3_D9: U8018.D11(CAM3_D[9]) ; also on sheet 21
CAM3_D10: U8018.T12(CAM3_D[10]) ; also on sheet 21
CAM3_D11: U8018.C7(CAM3_D[11]) ; also on sheet 21
CAM3_D12: U8018.V14(CAM3_D[12]) ; also on sheet 21
CAM3_D13: U8018.P16(CAM3_D[13]) ; also on sheet 21
CAM3_D14: U8018.D15(CAM3_D[14]) ; also on sheet 21
CAM3_D15: U8018.U11(CAM3_D[15]) ; also on sheet 21
CAM3_DE: U8018.K3(CAM3_DE) ; also on sheet 21
CAM3_HS: U8018.U12(CAM3_HS) ; also on sheet 21
CAM3_PCLK: U8018.V5(CAM3_PCLK) ; also on sheet 21
CAM3_VS: U8018.D2(CAM3_VS) ; also on sheet 21
CAM4_D0: U8018.E15(CAM4_D[0]) ; also on sheet 21
CAM4_D1: U8018.F10(CAM4_D[1]) ; also on sheet 21
CAM4_D2: U8018.T17(CAM4_D[2]) ; also on sheet 21
CAM4_D3: U8018.D7(CAM4_D[3]) ; also on sheet 21
CAM4_D4: U8018.G14(CAM4_D[4]) ; also on sheet 21
CAM4_D5: U8018.R16(CAM4_D[5]) ; also on sheet 21
CAM4_D6: U8018.C16(CAM4_D[6]) ; also on sheet 21
CAM4_D7: U8018.R13(CAM4_D[7]) ; also on sheet 21
CAM4_D8: U8018.A15(CAM4_D[8]) ; also on sheet 21
CAM4_D9: U8018.N9(CAM4_D[9]) ; also on sheet 21
CAM4_D10: U8018.P13(CAM4_D[10]) ; also on sheet 21
CAM4_D11: U8018.C8(CAM4_D[11]) ; also on sheet 21
CAM4_HS: U8018.G6(CAM4_HS) ; also on sheet 21
CAM4_PCLK: U8018.P8(CAM4_PCLK) ; also on sheet 21
CAM4_VS: U8018.F11(CAM4_VS) ; also on sheet 21
CEC_A: R9435.2 U8003.61(CEC) U8005.16(CE_REMOTE_IN)
F_HDMI_IN1_RX0+: FL8001.4 P8000.7(D0+) U8005.10(TMDSI_D0+) U8005.29(TMDSO_D0+)
F_HDMI_IN1_RX0-: FL8001.1 P8000.9(D0-) U8005.12(TMDSI_D0-) U8005.27(TMDSO_D0-)
F_HDMI_IN1_RX1+: FL8002.4 P8000.4(D1+) U8005.7(TMDSI_D1+) U8005.32(TMDSO_D1+)
F_HDMI_IN1_RX1-: FL8002.1 P8000.6(D1-) U8005.9(TMDSI_D1-) U8005.30(TMDSO_D1-)
F_HDMI_IN1_RX2+: FL8003.4 P8000.1(D2+) U8005.4(TMDSI_D2+) U8005.35(TMDSO_D2+)
F_HDMI_IN1_RX2-: FL8003.1 P8000.3(D2-) U8005.6(TMDSI_D2-) U8005.33(TMDSO_D2-)
F_HDMI_IN1_RXC+: FL8000.4 P8000.10(CK+) U8005.13(TMDSI_CK+) U8005.26(TMDSO_CK+)
F_HDMI_IN1_RXC-: FL8000.1 P8000.12(CK-) U8005.15(TMDSI_CK-) U8005.24(TMDSO_CK-)
FPD_B0: U8018.G5(FPD_D[0]) ; also on sheet 19
FPD_B1: U8018.C5(FPD_D[1]) ; also on sheet 19
FPD_B2: U8018.D18(FPD_D[2]) ; also on sheet 19
FPD_B3: U8018.B5(FPD_D[3]) ; also on sheet 19
FPD_B4: U8018.N17(FPD_D[4]) ; also on sheet 19
FPD_B5: U8018.V10(FPD_D[5]) ; also on sheet 19
FPD_B6: U8018.R10(FPD_D[6]) ; also on sheet 19
FPD_B7: U8018.D17(FPD_D[7]) ; also on sheet 19
FPD_DE: U8018.R2(FPD_DE) ; also on sheet 19
FPD_G0: U8018.F6(FPD_D[8]) ; also on sheet 19
FPD_G1: U8018.M1(FPD_D[9]) ; also on sheet 19
FPD_G2: U8018.L4(FPD_D[10]) ; also on sheet 19
FPD_G3: U8018.H6(FPD_D[11]) ; also on sheet 19
FPD_G4: U8018.R11(FPD_D[12]) ; also on sheet 19
FPD_G5: U8018.P17(FPD_D[13]) ; also on sheet 19
FPD_G6: U8018.H4(FPD_D[14]) ; also on sheet 19
FPD_G7: U8018.N12(FPD_D[15]) ; also on sheet 19
FPD_HS: U8018.A8(FPD_HS) ; also on sheet 19
FPD_PCLK: U8018.T5(FPD_PCLK) ; also on sheet 19
FPD_R0: U8018.E5(FPD_D[16]) ; also on sheet 19
FPD_R1: U8018.B4(FPD_D[17]) ; also on sheet 19
FPD_R2: U8018.F1(FPD_D[18]) ; also on sheet 19
FPD_R3: U8018.F7(FPD_D[19]) ; also on sheet 19
FPD_R4: U8018.T2(FPD_D[20]) ; also on sheet 19
FPD_R5: U8018.U1(FPD_D[21]) ; also on sheet 19
FPD_R6: U8018.L5(FPD_D[22]) ; also on sheet 19
FPD_R7: U8018.K6(FPD_D[23]) ; also on sheet 19
FPD_VS: U8018.B10(FPD_VS) ; also on sheet 19
FTDI_TCK: R9201.1 ; also on sheet 10
FTDI_TDI: R9203.1 ; also on sheet 10
FTDI_TDO: R9202.1 ; also on sheet 10
FTDI_TMS: R9204.1 ; also on sheet 10
HDMI_D0: U8019.P10(OUT_HDMI[0]) ; also on sheet 17
HDMI_D1: U8019.F15(OUT_HDMI[1]) ; also on sheet 17
HDMI_D2: U8019.C11(OUT_HDMI[2]) ; also on sheet 17
HDMI_D3: U8019.R6(OUT_HDMI[3]) ; also on sheet 17
HDMI_D4: U8019.M15(OUT_HDMI[4]) ; also on sheet 17
HDMI_D5: U8019.M16(OUT_HDMI[5]) ; also on sheet 17
HDMI_D6: U8019.A4(OUT_HDMI[6]) ; also on sheet 17
HDMI_D7: U8019.J14(OUT_HDMI[7]) ; also on sheet 17
HDMI_D8: U8019.F14(OUT_HDMI[8]) ; also on sheet 17
HDMI_D9: U8019.R5(OUT_HDMI[9]) ; also on sheet 17
HDMI_D10: U8019.P4(OUT_HDMI[10]) ; also on sheet 17
HDMI_D11: U8019.H16(OUT_HDMI[11]) ; also on sheet 17
HDMI_D12: U8019.A13(OUT_HDMI[12]) ; also on sheet 17
HDMI_D13: U8019.C9(OUT_HDMI[13]) ; also on sheet 17
HDMI_D14: U8019.B14(OUT_HDMI[14]) ; also on sheet 17
HDMI_D15: U8019.T6(OUT_HDMI[15]) ; also on sheet 17
HDMI_D16: U8019.E4(OUT_HDMI[16]) ; also on sheet 17
HDMI_D17: U8019.A10(OUT_HDMI[17]) ; also on sheet 17
HDMI_D18: U8019.D16(OUT_HDMI[18]) ; also on sheet 17
HDMI_D19: U8019.H2(OUT_HDMI[19]) ; also on sheet 17
HDMI_D20: U8019.F1(OUT_HDMI[20]) ; also on sheet 17
HDMI_D21: U8019.B10(OUT_HDMI[21]) ; also on sheet 17
HDMI_D22: U8019.B11(OUT_HDMI[22]) ; also on sheet 17
HDMI_D23: U8019.B3(OUT_HDMI[23]) ; also on sheet 17
HDMI_DEN: R9253.2 ; also on sheet 17
HDMI_HSYNC: R9254.2 ; also on sheet 17
HDMI_I2C2_SCL: R8026.1 RU8000.4(O) U8003.53(SCL)
HDMI_I2C2_SDA: R8027.1 RU8001.4(O) U8003.54(SDA)
HDMI_I2C2_SELN: R8022.1 RU8000.1(OE) RU8001.1(OE) SW8000.3(A3)
HDMI_IN1_DSCL: R8035.1 U8000.2(1B1) U8003.62(DDCA_SCL) U8005.17(DDC_CLK_IN)
HDMI_IN1_DSDA: R8036.2 U8000.5(2B1) U8003.63(DDCA_SDA) U8005.18(DDC_DAT_IN)
HDMI_IN1_HPD: R8037.1 R8038.2 U8003.1(HPA_A/INT2) U8005.19(HOTPLUG_DET_IN)
HDMI_IN1_RX0+: FL8001.3 U8003.7(RXA_0+)
HDMI_IN1_RX0-: FL8001.2 U8003.6(RXA_0-)
HDMI_IN1_RX1+: FL8002.3 U8003.10(RXA_1+)
HDMI_IN1_RX1-: FL8002.2 U8003.9(RXA_1-)
HDMI_IN1_RX2+: FL8003.3 U8003.13(RXA_2+)
HDMI_IN1_RX2-: FL8003.2 U8003.12(RXA_2-)
HDMI_IN1_RXC+: FL8000.3 U8003.4(RXA_C+)
HDMI_IN1_RXC-: FL8000.2 U8003.3(RXA_C-)
HDMI_INT: R8029.1 U8003.55(INT1) ; also on sheet 8
HDMI_INTn: U8019.J1(HDMI_INT) ; also on sheet 17
HDMI_P1_5V_CBL: C8047.1 P8000.18(+5V) R8042.1 R8043.1 R8046.2 R8048.1 RV8000.2 TP8002.1(TP)
HDMI_P1_P1PWR5V: C8007.2 R8048.2 U8003.64(RXA_5V)
HDMI_PCLK: R9256.2 ; also on sheet 17
HDMI_RSTn: U8019.M3(HDM_RST) ; also on sheet 17
HDMI_VSYNC: R9255.2 ; also on sheet 17
IOEXP2_P04: R9363.1 U8021.2(A) ; also on sheet 8
IOEXP2_P05: R9364.1 TP8010.1(TP) U8019.J15(RESERVED_PULLUP) ; also on sheet 8
IOEXP2_P20: TP8020.1(TP) U8018.B15(VISIBILITY[2]) ; also on sheet 8 31
IOEXP2_P21: TP8019.1(TP) U8018.P3(VISIBILITY[1]) ; also on sheet 8 31
IOEXP2_P22: TP8011.1(TP) U8019.M8(RESERVED_PULLUP) ; also on sheet 8 31
IOEXP2_P23: TP8012.1(TP) U8019.N15(RESERVED_PULLUP) ; also on sheet 8 31
IOEXP2_P24: TP8013.1(TP) U8019.R12(RESERVED_PULLUP) ; also on sheet 8
ISR_TCK: J1.1 R73.2 R9201.2 U8018.R4(TCK) U8019.P3(TCK)
ISR_TDI: J1.9 R62.1 R9204.2 U8018.M7(TDI)
ISR_TDO: J1.3 R9202.2 U8019.M5(TDO)
ISR_TDO_VMUX1: R9420.1 U8019.L6(TDI)
ISR_TMS: J1.5 R68.1 R9203.2 U8018.P5(TMS) U8019.N4(TMS)
LCD_B0: U8019.T10(OUT_EXP[0]) ; also on sheet 16
LCD_B1: U8019.D14(OUT_EXP[1]) ; also on sheet 16
LCD_B2: U8019.B13(OUT_EXP[2]) ; also on sheet 16
LCD_B3: U8019.L2(OUT_EXP[3]) ; also on sheet 16
LCD_B4: U8019.T15(OUT_EXP[4]) ; also on sheet 16
LCD_B5: U8019.M14(OUT_EXP[5]) ; also on sheet 16
LCD_B6: U8019.C4(OUT_EXP[6]) ; also on sheet 16
LCD_B7: U8019.J16(OUT_EXP[7]) ; also on sheet 16
LCD_DE: R9245.2 ; also on sheet 16
LCD_G0: U8019.H15(OUT_EXP[8]) ; also on sheet 16
LCD_G1: U8019.R4(OUT_EXP[9]) ; also on sheet 16
LCD_G2: U8019.P6(OUT_EXP[10]) ; also on sheet 16
LCD_G3: U8019.H14(OUT_EXP[11]) ; also on sheet 16
LCD_G4: U8019.G16(OUT_EXP[12]) ; also on sheet 16
LCD_G5: U8019.C8(OUT_EXP[13]) ; also on sheet 16
LCD_G6: U8019.C15(OUT_EXP[14]) ; also on sheet 16
LCD_G7: U8019.N5(OUT_EXP[15]) ; also on sheet 16
LCD_HS: R9246.2 ; also on sheet 16
LCD_PCLK: R9248.2 ; also on sheet 16
LCD_R0: U8019.B1(OUT_EXP[16]) ; also on sheet 16
LCD_R1: U8019.D15(OUT_EXP[17]) ; also on sheet 16
LCD_R2: U8019.E13(OUT_EXP[18]) ; also on sheet 16
LCD_R3: U8019.G1(OUT_EXP[19]) ; also on sheet 16
LCD_R4: U8019.E2(OUT_EXP[20]) ; also on sheet 16
LCD_R5: U8019.A9(OUT_EXP[21]) ; also on sheet 16
LCD_R6: U8019.R11(OUT_EXP[22]) ; also on sheet 16
LCD_R7: U8019.C2(OUT_EXP[23]) ; also on sheet 16
LCD_VS: R9247.2 ; also on sheet 16
LI_CAM_D0: U8018.P18(LI_D[0]) ; also on sheet 20
LI_CAM_D1: U8018.D14(LI_D[1]) ; also on sheet 20
LI_CAM_D2: U8018.E16(LI_D[2]) ; also on sheet 20
LI_CAM_D3: U8018.C17(LI_D[3]) ; also on sheet 20
LI_CAM_D4: U8018.L14(LI_D[4]) ; also on sheet 20
LI_CAM_D5: U8018.G18(LI_D[5]) ; also on sheet 20
LI_CAM_D6: U8018.H18(LI_D[6]) ; also on sheet 20
LI_CAM_D7: U8018.H14(LI_D[7]) ; also on sheet 20
LI_CAM_D8: U8018.H16(LI_D[8]) ; also on sheet 20
LI_CAM_D9: U8018.K17(LI_D[9]) ; also on sheet 20
LI_CAM_D10: U8018.M15(LI_D[10]) ; also on sheet 20
LI_CAM_D11: U8018.U7(LI_D[11]) ; also on sheet 20
LI_CAM_D12: U8018.F13(LI_D[12]) ; also on sheet 20
LI_CAM_D13: U8018.U15(LI_D[13]) ; also on sheet 20
LI_CAM_RESETn_OD: U8018.T6(LI_RST) ; also on sheet 20
LI_HSYNC: U8018.D9(LI_HS) ; also on sheet 20
LI_PCLK: U8018.U6(LI_PCLK) ; also on sheet 20
LI_VSYNC: U8018.E11(LI_VS) ; also on sheet 20
MAB1_VOUT1_CLK: TP8124.1(TP) U8019.H5(IN_VOUT_PCLK) ; also on sheet 30
MAB1_VOUT1_D0: U8019.R9(IN_VOUT[0]) ; also on sheet 30
MAB1_VOUT1_D1: U8019.B5(IN_VOUT[1]) ; also on sheet 30
MAB1_VOUT1_D2: U8019.M9(IN_VOUT[2]) ; also on sheet 30
MAB1_VOUT1_D3: U8019.A11(IN_VOUT[3]) ; also on sheet 30
MAB1_VOUT1_D4: U8019.T2(IN_VOUT[4]) ; also on sheet 30
MAB1_VOUT1_D5: U8019.K15(IN_VOUT[5]) ; also on sheet 30
MAB1_VOUT1_D6: U8019.E16(IN_VOUT[6]) ; also on sheet 30
MAB1_VOUT1_D7: U8019.B12(IN_VOUT[7]) ; also on sheet 30
MAB1_VOUT1_DE: TP8121.1(TP) U8019.M1(IN_VOUT[24]/DE) ; also on sheet 30
MAB1_VOUT1_HSYNC: TP8122.1(TP) U8019.K2(IN_VOUT[25]/HSYNC) ; also on sheet 30
MAB1_VOUT1_VSYNC: TP8123.1(TP) U8019.N13(IN_VOUT[26]/VSHYN) ; also on sheet 30
MAB2_VIN1A_D16: U8018.A2(VIN1A_D[16]) ; also on sheet 30
MAB2_VIN1A_D17: U8018.D1(VIN1A_D[17]) ; also on sheet 30
MAB2_VIN1A_D18: U8018.B3(VIN1A_D[18]) ; also on sheet 30
MAB2_VIN1A_D19: U8018.B1(VIN1A_D[19]) ; also on sheet 30
MAB2_VIN1A_D20: U8018.M4(VIN1A_D[20]) ; also on sheet 30
MAB2_VIN1A_D21: U8018.N4(VIN1A_D[21]) ; also on sheet 30
MAB2_VIN1A_D22: U8018.N2(VIN1A_D[22]) ; also on sheet 30
MAB2_VIN1A_D23: U8018.J3(VIN1A_D[23]) ; also on sheet 30
MCB1_VOUT1_D08: U8019.F13(IN_VOUT[8]) ; also on sheet 30
MCB1_VOUT1_D09: U8019.M4(IN_VOUT[9]) ; also on sheet 30
MCB1_VOUT1_D10: U8019.L4(IN_VOUT[10]) ; also on sheet 30
MCB1_VOUT1_D11: U8019.G15(IN_VOUT[11]) ; also on sheet 30
MCB1_VOUT1_D12: U8019.F16(IN_VOUT[12]) ; also on sheet 30
MCB1_VOUT1_D13: U8019.A8(IN_VOUT[13]) ; also on sheet 30
MCB1_VOUT1_D14: U8019.P15(IN_VOUT[14]) ; also on sheet 30
MCB1_VOUT1_D15: U8019.T5(IN_VOUT[15]) ; also on sheet 30
MCB1_VOUT1_D16: U8019.E3(IN_VOUT[16]) ; also on sheet 30
MCB1_VOUT1_D17: U8019.T9(IN_VOUT[17]) ; also on sheet 30
MCB1_VOUT1_D18: U8019.E15(IN_VOUT[18]) ; also on sheet 30
MCB1_VOUT1_D19: U8019.H1(IN_VOUT[19]) ; also on sheet 30
MCB1_VOUT1_D20: U8019.F3(IN_VOUT[20]) ; also on sheet 30
MCB1_VOUT1_D21: U8019.K16(IN_VOUT[21]) ; also on sheet 30
MCB1_VOUT1_D22: U8019.K14(IN_VOUT[22]) ; also on sheet 30
MCB1_VOUT1_D23: U8019.H3(IN_VOUT[23]) ; also on sheet 30
MCB2_VIN2A_D0: U8018.K18(VIN2A_D[0]) ; also on sheet 30
MCB2_VIN2A_D1: U8018.E10(VIN2A_D[1]) ; also on sheet 30
MCB2_VIN2A_D2: U8018.R14(VIN2A_D[2]) ; also on sheet 30
MCB2_VIN2A_D3: U8018.D8(VIN2A_D[3]) ; also on sheet 30
MCB2_VIN2A_D4: U8018.B18(VIN2A_D[4]) ; also on sheet 30
MCB2_VIN2A_D5: U8018.N15(VIN2A_D[5]) ; also on sheet 30
MCB2_VIN2A_D6: U8018.J14(VIN2A_D[6]) ; also on sheet 30
MCB2_VIN2A_D7: U8018.L15(VIN2A_D[7]) ; also on sheet 30
MDB1_VIN1A_CLK0: R9235.2 TP8130.1(TP) ; also on sheet 34
MDB1_VIN1A_D0: U8018.K13(VIN1A_D[0]) ; also on sheet 34
MDB1_VIN1A_D1: U8018.B7(VIN1A_D[1]) ; also on sheet 34
MDB1_VIN1A_D2: U8018.J15(VIN1A_D[2]) ; also on sheet 34
MDB1_VIN1A_D3: U8018.E8(VIN1A_D[3]) ; also on sheet 34
MDB1_VIN1A_D4: U8018.F18(VIN1A_D[4]) ; also on sheet 34
MDB1_VIN1A_D5: U8018.M13(VIN1A_D[5]) ; also on sheet 34
MDB1_VIN1A_D6: U8018.M12(VIN1A_D[6]) ; also on sheet 34
MDB1_VIN1A_D7: U8018.M18(VIN1A_D[7]) ; also on sheet 34
MDB1_VIN1A_VSYNC0: R9236.2 TP8131.1(TP) ; also on sheet 34
MDB2_CPI_DATA0: U8018.J13(CPI_D[0]) ; also on sheet 34
MDB2_CPI_DATA1: U8018.H15(CPI_D[1]) ; also on sheet 34
MDB2_CPI_DATA2: U8018.J16(CPI_D[2]) ; also on sheet 34
MDB2_CPI_DATA3: U8018.F15(CPI_D[3]) ; also on sheet 34
MDB2_CPI_DATA4: U8018.G13(CPI_D[4]) ; also on sheet 34
MDB2_CPI_DATA5: U8018.L13(CPI_D[5]) ; also on sheet 34
MDB2_CPI_DATA6: U8018.J18(CPI_D[6]) ; also on sheet 34
MDB2_CPI_DATA7: U8018.L16(CPI_D[7]) ; also on sheet 34
MDB2_CPI_DATA8: U8018.C15(CPI_D[8]) ; also on sheet 34
MDB2_CPI_DATA9: U8018.D13(CPI_D[9]) ; also on sheet 34
MDB2_CPI_HSYNC: R9230.2 TP8125.1(TP) ; also on sheet 34
MDB2_CPI_PCLK: R9231.2 TP8126.1(TP) ; also on sheet 34
MEB1_VIN2B_CLK1: R9243.2 TP8138.1(TP) ; also on sheet 34
MEB1_VIN2B_HSYNC1: R9242.2 TP8137.1(TP) ; also on sheet 34
MEB1_VIN2B_VSYNC1: R9244.2 TP8139.1(TP) ; also on sheet 34
MEB2_CPI_DATA10: U8018.N10(CPI_D[10]) ; also on sheet 34
MEB2_CPI_DATA11: U8018.L2(CPI_D[11]) ; also on sheet 34
MEB2_CPI_DATA12: U8018.R18(CPI_D[12]) ; also on sheet 34
MEB2_CPI_DATA13: U8018.U13(CPI_D[13]) ; also on sheet 34
MEB2_CPI_DATA14: U8018.U5(CPI_D[14]) ; also on sheet 34
MEB2_CPI_DATA15: U8018.L6(CPI_D[15]) ; also on sheet 34
MEB2_CPI_VSYNC: R9232.2 TP8127.1(TP) ; also on sheet 34
MJB1_VIN2A_CLK0: R9240.2 TP8135.1(TP) ; also on sheet 32
MJB1_VIN2A_HSYNC0: R9239.2 TP8134.1(TP) ; also on sheet 32
MJB1_VIN2A_VSYNC0: R9241.2 TP8136.1(TP) ; also on sheet 32
MUX_CNTL0: U8019.T8(MUX_CNTL[0]) ; also on sheet 8 9 31
MUX_CNTL1: U8019.L14(MUX_CNTL[1]) ; also on sheet 8
MUX_CNTL2: U8019.L13(MUX_CNTL[2]) ; also on sheet 8
MUX_CNTL3: U8019.D11(MUX_CNTL[3]) ; also on sheet 8
MUX_CNTL4: U8019.A6(MUX_CNTL[4]) ; also on sheet 8
MUX_CNTL5: U8019.K3(MUX_CNTL[5]) ; also on sheet 8
MUX_CNTL6: U8019.T12(MUX_CNTL[6]) ; also on sheet 8
MUX_CNTL7: U8019.P13(MUX_CNTL[7]) ; also on sheet 8
MUX_CNTL8: U8019.D5(MUX_CNTL[8]) ; also on sheet 8
MUX_CNTL9: U8019.T7(MUX_CNTL[9]) ; also on sheet 8
MUX_CNTL10: U8019.D1(MUX_CNTL[10]) ; also on sheet 8
MUX_CNTL11: U8019.C5(MUX_CNTL[11]) ; also on sheet 8
MUX_CNTL12: U8019.C10(MUX_CNTL[12]) ; also on sheet 8
MUX_CNTL13: TP8008.1(TP) U8019.B4(RESERVED_PULLUP) ; also on sheet 8
OV_1HREF: U8018.B8(OV_HS) ; also on sheet 20
OV_1PCLK: U8018.P9(OV_PCLK) ; also on sheet 20
OV_1VSYNC: U8018.C9(OV_VS) ; also on sheet 20
OV_1Y0: U8018.N16(OV_D[0]) ; also on sheet 20
OV_1Y1: U8018.F16(OV_D[1]) ; also on sheet 20
OV_1Y2: U8018.H13(OV_D[2]) ; also on sheet 20
OV_1Y3: U8018.G17(OV_D[3]) ; also on sheet 20
OV_1Y4: U8018.J17(OV_D[4]) ; also on sheet 20
OV_1Y5: U8018.K16(OV_D[5]) ; also on sheet 20
OV_1Y6: U8018.K14(OV_D[6]) ; also on sheet 20
OV_1Y7: U8018.M17(OV_D[7]) ; also on sheet 20
OV_1Y8: U8018.G12(OV_D[8]) ; also on sheet 20
OV_1Y9: U8018.L18(OV_D[9]) ; also on sheet 20
OV_1Y10: U8018.C14(OV_1Y10) ; also on sheet 20
OV_1Y11: U8018.U10(OV_1Y11) ; also on sheet 20
OV_PWDN: U8018.P6(OV_RST) ; also on sheet 20
PORz: U8021.1(B) U8022.1(B) U8022.2(A) ; also on sheet 4 13
R_MCAN_RX/CAM_nRESET/VIN2A_VSYNC0/SPI1_CS3/UART3_TXD/GPMC_CS7/VIN1B_VSYNC1/GPIO4_12: R9238.2 TP8133.1(TP) ; also on sheet 7
R_VOUT1_FLD/MCASP1_FSX/VIN1A_D14/CLKOUT2/GPIO2_22: U8019.F2(CPU_INT) ; also on sheet 7
RSTOUTn: TP8009.1(TP) U8019.B16(RESERVED_PULLUP) ; also on sheet 4 8 9 22
SEL_HDMI_INn: Q2022.1(G) R9177.2(P2) U8000.15(~{OE}) ; also on sheet 8 31
SEL_MA0: R9343.2 U8019.C12(MUX_SEL[0]) ; also on sheet 30
SEL_MA1: R9342.2 U8019.R10(MUX_SEL[1]) ; also on sheet 30
SEL_MC0: R9341.2 U8019.C6(MUX_SEL[4]) ; also on sheet 30
SEL_MC1: R9340.2 U8019.P7(MUX_SEL[5]) ; also on sheet 30
SEL_MD_E0: R9339.2 U8019.J2(MUX_SEL[6]) ; also on sheet 34
SEL_MD_E1: R9338.2 U8019.R8(MUX_SEL[7]) ; also on sheet 34
SEL_MF0: R9337.2 U8019.N12(MUX_SEL[8]) ; also on sheet 34
SEL_MF1: R9336.2 U8019.R14(MUX_SEL[9]) ; also on sheet 34
SEL_MH0: R9335.2 U8019.B6(MUX_SEL[10]) ; also on sheet 34
SEL_MJ0: R9334.2 U8019.B8(MUX_SEL[11]) ; also on sheet 32
SEL_MJ1: R9333.2 U8019.R7(MUX_SEL[12]) ; also on sheet 32
SEL_MK0: R9332.2 U8019.E1(MUX_SEL[13]) ; also on sheet 32
SEL_MM0: R9331.2 U8019.B7(MUX_SEL[14]) ; also on sheet 32
SEL_MM1: R9330.2 U8019.P9(MUX_SEL[15]) ; also on sheet 32
TS_LCD_IRQ: U8019.A2(EXP_INT) ; also on sheet 16
VHDMI_IN_1V8: C8008.1 C8017.1 C8019.1 L8000.2 L8003.1 L8004.1 R8008.1 U8004.9(VOUT1) U8004.10(VOUT2)
VHDMI_IN_3V3: C8001.1 C8003.1 C8009.1 L8001.1 L8002.1 R8001.1 R9433.1 U8002.9(VOUT1) U8002.10(VOUT2)
VHDMI_IN_CVDD: C8004.1 C8024.1 C8030.1 L8000.1 U8003.2(CVDD) U8003.14(CVDD_1)
VHDMI_IN_DVDD: C8015.1 C8025.1 C8029.1 C8034.1 C8035.1 L8004.2 U8003.24(DVDD) U8003.40(DVDD_1) U8003.52(DVDD_2) U8003.60(DVDD_3)
VHDMI_IN_DVDDIO: C8010.1 C8022.2 C8027.1 C8031.1 C8040.1 C8042.1 L8001.2 R8011.1 R8012.1 R8013.1 R8015.1 R8016.1 R8019.1 R8026.2 R8027.2 R8029.2 R8031.2 R8035.2 R8036.1 R8038.1 R8041.2 R8045.1 R9434.1(P1) R9435.1 U8001.8(VCC) U8003.23(DVDDIO) U8003.34(DVDDIO_1) U8003.44(DVDDIO_2)
VHDMI_IN_PVDD: C8038.1 C8231.1 L8003.2 U8003.57(PVDD)
VHDMI_IN_TVDD: C8011.1 C8039.1 C8041.1 C8043.1 L8002.2 U8003.5(TVDD) U8003.8(TVDD_1) U8003.11(TVDD_2)
VI_DE: R8004.2 TP8120.1(TP) U8018.P2(HDMI_DE)
VI_HSYNC: R8002.2 TP8119.1(TP) U8018.T9(HDMI_HS)
VI_ODCK: R8005.2 TP8117.1(TP) U8018.N5(HDMI_PCLK)
VI_QE0: RN8005.4(R4A) U8018.G4(HDMI_D[0])
VI_QE1: RN8005.3(R3A) U8018.F8(HDMI_D[1])
VI_QE2: RN8005.2(R2A) U8018.F12(HDMI_D[2])
VI_QE3: RN8005.1(R1A) U8018.A5(HDMI_D[3])
VI_QE4: RN8004.4(R4A) U8018.G15(HDMI_D[4])
VI_QE5: RN8004.3(R3A) U8018.P12(HDMI_D[5])
VI_QE6: RN8004.2(R2A) U8018.V11(HDMI_D[6])
VI_QE7: RN8004.1(R1A) U8018.U16(HDMI_D[7])
VI_QE8: RN8003.4(R4A) U8018.G1(HDMI_D[8])
VI_QE9: RN8003.3(R3A) U8018.R1(HDMI_D[9])
VI_QE10: RN8003.2(R2A) U8018.M6(HDMI_D[10])
VI_QE11: RN8003.1(R1A) U8018.H5(HDMI_D[11])
VI_QE12: RN8000.4(R4A) U8018.V12(HDMI_D[12])
VI_QE13: RN8000.3(R3A) U8018.A17(HDMI_D[13])
VI_QE14: RN8000.2(R2A) U8018.E4(HDMI_D[14])
VI_QE15: RN8000.1(R1A) U8018.U14(HDMI_D[15])
VI_QE16: RN8001.4(R4A) U8018.C4(HDMI_D[16])
VI_QE17: RN8001.3(R3A) U8018.D6(HDMI_D[17])
VI_QE18: RN8001.2(R2A) U8018.C3(HDMI_D[18])
VI_QE19: RN8001.1(R1A) U8018.D3(HDMI_D[19])
VI_QE20: RN8002.4(R4A) U8018.R3(HDMI_D[20])
VI_QE21: RN8002.3(R3A) U8018.V2(HDMI_D[21])
VI_QE22: RN8002.2(R2A) U8018.L3(HDMI_D[22])
VI_QE23: RN8002.1(R1A) U8018.J4(HDMI_D[23])
VI_RESETn: R8031.1 TP8066.1(TP) U8003.56(*RESET) U8018.R6(HDMI_RST)
VI_VSYNC: R8003.2 TP8118.1(TP) U8018.A11(HDMI_VS)
VOFPD_CLK: R9252.2 ; also on sheet 18
VOFPD_D0: U8019.C7(OUT_FPD[0]) ; also on sheet 18
VOFPD_D1: U8019.E14(OUT_FPD[1]) ; also on sheet 18
VOFPD_D2: U8019.A12(OUT_FPD[2]) ; also on sheet 18
VOFPD_D3: U8019.P5(OUT_FPD[3]) ; also on sheet 18
VOFPD_D4: U8019.P14(OUT_FPD[4]) ; also on sheet 18
VOFPD_D5: U8019.N14(OUT_FPD[5]) ; also on sheet 18
VOFPD_D6: U8019.D4(OUT_FPD[6]) ; also on sheet 18
VOFPD_D7: U8019.H12(OUT_FPD[7]) ; also on sheet 18
VOFPD_D8: U8019.G14(OUT_FPD[8]) ; also on sheet 18
VOFPD_D9: U8019.R3(OUT_FPD[9]) ; also on sheet 18
VOFPD_D10: U8019.R1(OUT_FPD[10]) ; also on sheet 18
VOFPD_D11: U8019.J12(OUT_FPD[11]) ; also on sheet 18
VOFPD_D12: U8019.C13(OUT_FPD[12]) ; also on sheet 18
VOFPD_D13: U8019.D13(OUT_FPD[13]) ; also on sheet 18
VOFPD_D14: U8019.C14(OUT_FPD[14]) ; also on sheet 18
VOFPD_D15: U8019.T4(OUT_FPD[15]) ; also on sheet 18
VOFPD_D16: U8019.D3(OUT_FPD[16]) ; also on sheet 18
VOFPD_D17: U8019.A7(OUT_FPD[17]) ; also on sheet 18
VOFPD_D18: U8019.A15(OUT_FPD[18]) ; also on sheet 18
VOFPD_D19: U8019.J3(OUT_FPD[19]) ; also on sheet 18
VOFPD_D20: U8019.D2(OUT_FPD[20]) ; also on sheet 18
VOFPD_D21: U8019.B9(OUT_FPD[21]) ; also on sheet 18
VOFPD_D22: U8019.D12(OUT_FPD[22]) ; also on sheet 18
VOFPD_D23: U8019.C3(OUT_FPD[23]) ; also on sheet 18
VOFPD_DE: R9249.2 ; also on sheet 18
VOFPD_HSYNC: R9250.2 ; also on sheet 18
VOFPD_INTB: U8019.G2(FPD_INT) ; also on sheet 18
VOFPD_VSYNC: R9251.2 ; also on sheet 18
VOUT_MAP0: U8019.A5(MODE_SEL[0]) ; also on sheet 8
VOUT_MAP1: U8019.P8(MODE_SEL[1]) ; also on sheet 8
VOUT_MAP2: U8019.P11(MODE_SEL[2]) ; also on sheet 8
VPRH_3V3: C8016.1 C8020.1 C8021.1 R8006.1(P1) R8020.2 R8022.2 RU8000.5(VCC) RU8001.5(VCC) U8000.16(VCC) U8004.1(IN1) U8004.2(IN2) U8004.4(BIAS) ; also on sheet 8 9 11 15 16 17 18 19 20 21 22 30 31 32 34 35
VPRH_5V0: C8000.1 C8044.1 C8147.2 U8002.1(IN1) U8002.2(IN2) U8002.4(BIAS) U8005.1(5V_SUPPLY) U8023.1(IN) ; also on sheet 14 16 17 20 21 35
VPRH_DV: C8098.1 C8099.1 C8100.1 C8101.1 C8102.1 C8103.1 C8106.1 C8107.1 C8108.1 C8109.1 C8110.1 C8111.1 C8112.1 C8113.1 C8121.1 C8122.1 C8123.1 C8124.1 C8125.1 C8126.1 C8127.1 C8128.1 C8129.1 C8130.1 C8131.1 C8132.1 C8133.1 C8134.1 C8144.1 C8145.1 J1.4 R62.2 R68.2 R9177.1(P1) R9363.2 R9364.2 U8018.A3(VCCIO2) U8018.A16(VCCIO2) U8018.C1(VCCIO1) U8018.C18(VCCIO3) U8018.G9(VCCIO2) U8018.G10(VCCIO2) U8018.J7(VCCIO1) U8018.J12(VCCIO3) U8018.K7(VCCIO1) U8018.K12(VCCIO3) U8018.M9(VCCIO4) U8018.M10(VCCIO4) U8018.T1(VCCIO1) U8018.T18(VCCIO3) U8018.V3(VCCIO4) U8018.V16(VCCIO4) U8019.A3(VCCIO2) U8019.A14(VCCIO2) U8019.C1(VCCIO1) U8019.C16(VCCIO2) U8019.F8(VCCIO2) U8019.F9(VCCIO2) U8019.H6(VCCIO1) U8019.H11(VCCIO2) U8019.J6(VCCIO1) U8019.J11(VCCIO2) U8019.L8(VCCIO1) U8019.L9(VCCIO1) U8019.P1(VCCIO1) U8019.P16(VCCIO2) U8019.T3(VCCIO1) U8019.T14(VCCIO1) U8021.5(VCC) U8022.5(VCC) ; also on sheet 4 7 8 9 10 11 13 15 16 17 18 19 20 21 22 28 31 35 36
VSEL_2V5: C8146.1 R9329.2 R9330.1 R9331.1 R9332.1 R9333.1 R9334.1 R9335.1 R9336.1 R9337.1 R9338.1 R9339.1 R9340.1 R9341.1 R9342.1 R9343.1 U8023.5(OUT)
VSYS_3V3: C8114.1 C8115.1 C8116.1 C8117.1 C8118.1 C8119.1 C8120.1 C8135.1 C8136.1 C8137.1 C8138.1 C8139.1 C8140.1 C8141.1 U8018.G11(VCCINT) U8018.H12(VCCINT) U8018.J9(VCCINT) U8018.J11(VCCINT) U8018.K8(VCCINT) U8018.K10(VCCINT) U8018.L7(VCCINT) U8018.M8(VCCINT) U8019.F10(VCCINT) U8019.G11(VCCINT) U8019.H8(VCCINT) U8019.H10(VCCINT) U8019.J7(VCCINT_J10) U8019.J9(VCCINT) U8019.K6(VCCINT) U8019.L7(VCCINT) ; also on sheet 6 12 13 14 16 32 37
N26210503: U8018.U4(SYS_RST) U8021.4(Y)
N26246465: R9420.2 U8018.N6(TDO)
N26365776: U8019.G3(SYS_RST) U8022.4(Y)
N26370951: TP8034.1(TP) U8019.N16(MUX_SEL[2])
N26370952: TP8033.1(TP) U8019.R16(MUX_SEL[3])
N26374152: TP8014.1(TP) U8019.R13(RESERVED_PULLUP)
N26374154: TP8015.1(TP) U8019.T11(RESERVED_PULLUP)
N26374166: TP8016.1(TP) U8019.T13(RESERVED_PULLUP)
N26374184: TP8017.1(TP) U8019.P12(IN_VOUT_IOCLK)
N26374292: TP8021.1(TP) U8018.P7(VISIBILITY[3])
N26374295: TP8022.1(TP) U8018.A4(VISIBILITY[4])
N26374324: TP8027.1(TP) U8018.N11(VISIBILITY[0])
N26374340: TP8028.1(TP) U8018.T4(FPD_RST)
N26374436: R9230.1 U8018.A10(CPI_HS)
N26374439: R9231.1 U8018.V6(CPI_PCLK)
N26374442: R9232.1 U8018.A12(CPI_VS)
N26374898: R9233.1 U8018.U3(VIN1A_DEPCLKB)
N26374901: R9234.1 U8018.E9(VIN1A_HS)
N26374904: R9235.1 U8018.T8(VIN1A_PCLK)
N26374907: R9236.1 U8018.C10(VIN1A_VS)
N26374910: R9237.1 U8018.U9(VIN1B_HS)
N26374913: R9238.1 U8018.B14(VIN1B_VS)
N26374963: TP8029.1(TP) U8018.J6(VIN2A_DE)
N26375062: R9239.1 U8018.B13(VIN2A_HS)
N26375065: R9240.1 U8018.N8(VIN2A_PCLK)
N26375068: R9241.1 U8018.D10(VIN2A_VS)
N26375071: R9242.1 U8018.H1(VIN2B_HS)
N26375074: R9243.1 U8018.T7(VIN2B_PCLK)
N26375077: R9244.1 U8018.A14(VIN2B_VS)
N26375820: R9256.1 U8019.K1(OUT_HDMI_CLK)
N26375823: R9255.1 U8019.L16(OUT_HDMI[26]/VSYNC)
N26375826: R9254.1 U8019.N1(OUT_HDMI[25]/HSYNC)
N26375829: R9253.1 U8019.P2(OUT_HDMI[24]/DE)
N26375844: R9252.1 U8019.J5(OUT_FPD_CLK)
N26375847: R9251.1 U8019.L15(OUT_FPD[26]/VSYNC)
N26375850: R9250.1 U8019.L1(OUT_FPD[25]/HSYNC)
N26375853: R9249.1 U8019.N2(OUT_FPD[24]/DE)
N26375868: R9248.1 U8019.L3(OUT_EXP_CLK)
N26375871: R9247.1 U8019.M13(OUT_EXP[26]/VSYNC)
N26375874: R9246.1 U8019.M2(OUT_EXP[25]/HSYNC)
N26375877: R9245.1 U8019.N3(OUT_EXP[24]/DE)
N26550846: R9328.2 R9329.1 U8023.4(FB)
N29426933: C8037.1 R8034.1 U8003.59(XTALN) Y8000.2
N29426939: C8032.1 R8034.2 U8003.58(XTALP) Y8000.1
N29427148: RN8001.5(R4B) U8003.22(P16)
N29427150: RN8001.6(R3B) U8003.21(P17)
N29427152: RN8001.7(R2B) U8003.20(P18)
N29427154: RN8001.8(R1B) U8003.19(P19)
N29427156: RN8002.5(R4B) U8003.18(P20)
N29427158: RN8002.6(R3B) U8003.17(P21)
N29427160: RN8002.7(R2B) U8003.16(P22)
N29427162: RN8002.8(R1B) U8003.15(P23)
N29427164: Q2022.3(D) R8006.2(P2) U8002.5(EN)
N29427196: R9432.1 R9433.2 U8004.5(EN)
N29427234: C8002.1 U8002.7(SS)
N29427243: C8003.2 R8000.1 R8001.2 U8002.8(FB)
N29427292: C8018.1 U8004.7(SS)
N29427296: C8019.2 R8007.1 R8008.2 U8004.8(FB)
N29427886: R9298.1 RU8001.2(I)
N29428094: RN8005.5(R4B) U8003.43(P0)
N29428096: RN8005.6(R3B) U8003.42(P1)
N29428098: RN8005.7(R2B) U8003.41(P2)
N29428100: RN8005.8(R1B) U8003.39(P3)
N29428102: RN8004.5(R4B) U8003.38(P4)
N29428104: RN8004.6(R3B) U8003.37(P5)
N29428106: RN8004.7(R2B) U8003.36(P6)
N29428108: RN8004.8(R1B) U8003.35(P7)
N29428110: RN8003.5(R4B) U8003.33(P8)
N29428112: RN8003.6(R3B) U8003.32(P9)
N29428114: RN8003.7(R2B) U8003.31(P10)
N29428116: R9299.1 RU8000.2(I)
N29428118: RN8003.8(R1B) U8003.30(P11)
N29428120: RN8000.5(R4B) U8003.29(P12)
N29428122: RN8000.6(R3B) U8003.28(P13)
N29428124: RN8000.7(R2B) U8003.27(P14)
N29428126: RN8000.8(R1B) U8003.26(P15)
N29428174: R8003.1 R9434.2(P2) U8003.47(VS/FIELD/ALSB)
N29428789: R8005.1 U8003.25(LLC)
N29428795: R8004.1 U8003.45(DE)
N29428817: R8002.1 U8003.46(HS)
N29430899: P8000.19(HP_DET) R8046.1 R8047.1 U8005.20(HOTPLUG_DET_OUT)
N29431320: R8016.2 R8017.1 U8001.1(A0)
N29431340: C8045.1 R8041.1 U8005.2(LV_SUPPLY)
N29431430: R8013.2 SW8000.2(A2) U8001.7(WP)
N29431541: R8023.2 SW8000.1(A1) U8000.1(S)
N29431547: P8000.13(CE_REMOTE) R8045.2 U8005.23(CE_REMOTE_OUT)
N29431549: P8000.16(DDC_DATA) R8043.2 U8005.21(DDC_DAT_OUT)
N29431551: P8000.15(DDC_CLK) R8042.2 U8005.22(DDC_CLK_OUT)
N29431681: C8046.1 U8005.37(ESD_BYP)
N29431784: R8021.1 SW8000.6(B3)
N29431793: R8020.1 SW8000.8(B1)
N29431865: R8018.1 R8019.2 U8001.3(A2)
N29431943: R8014.1 R8015.2 U8001.2(A1)

Not connected (* = marked no-connect by the designer): J1 6 7 8; P8000 14(NC.14)*; SW8000 4(A4) 5(B4); U8000 9(3A) 12(4A); U8002 3(PG); U8003 48(AP)* 49(SCLK/INT2)* 50(LRCLK)* 51(MCLK/INT2)*; U8004 3(PG); U8005 38(NC.38); U8019 D6(NC) D7(NC) D8(NC) D9(NC) D10(NC) E5(NC) E6(NC) E7(NC) E8(NC) E9(NC) E10(NC) E11(NC) E12(NC) F4(NC) F5(NC) F6(NC) F11(NC) F12(NC) G4(NC) G5(NC) G12(NC) G13(NC) H4(NC) H13(NC) J4(NC) J13(NC) K4(NC) K5(NC) K12(NC) K13(NC) L5(NC) L11(NC) L12(NC) M6(NC) M7(NC) M10(NC) M11(NC) M12(NC) N6(NC) N7(NC) N8(NC) N9(NC) N10(NC) N11(NC)

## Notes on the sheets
sheet 23
- NP  - I2C ADDRESS 0x4C
  10K - I2C ADDRESS 0x4D
- ECS-286.3-18-23A-EN-TR
- 5V, VHDMI_IN_3V3, THEN VHDMI_IN_1V8
- VOUT = 0.8 * ( 1+Rtop/Rbottom )
- VOUT = 0.8 * ( 1+Rtop/Rbottom )
sheet 24
- BLANK
sheet 25
- DIFFERENTIAL PAIR
  100 OHM DIFFERENTIAL
  IMPEDANCE
  SHORT AND STRAIGHT AS
  POSSIBLE,
  MINIMUM NUMBER OF VIAS
- LOCATE AT THE END OF
  I2C NET FOR OPTIONAL
  PULLUP DUE TO EXCESSIVE
  TRACE LENGTH.
- SW1 OPEN: DEFAULT S=0,WP=1
sheet 26
- [VOUT_RSTn]
- MUX SELECTS OPERATE AS OPEN DRAIN WITH
  2.5V PULLUPS. THIS SUPPORTS VINmin WITH
  VDDSHV AT 1.8v.  CPLD I/O CAN HANDLE 2.5V WITH
  1.8V I/O VOLTAGE.
- 100mA max
sheet 27
- [VIP_RSTn]
- ADDED AFTER CPLD ROUTED, USING
  VISIBILITY 5-8.  TIMING CHECKS
  OK.
